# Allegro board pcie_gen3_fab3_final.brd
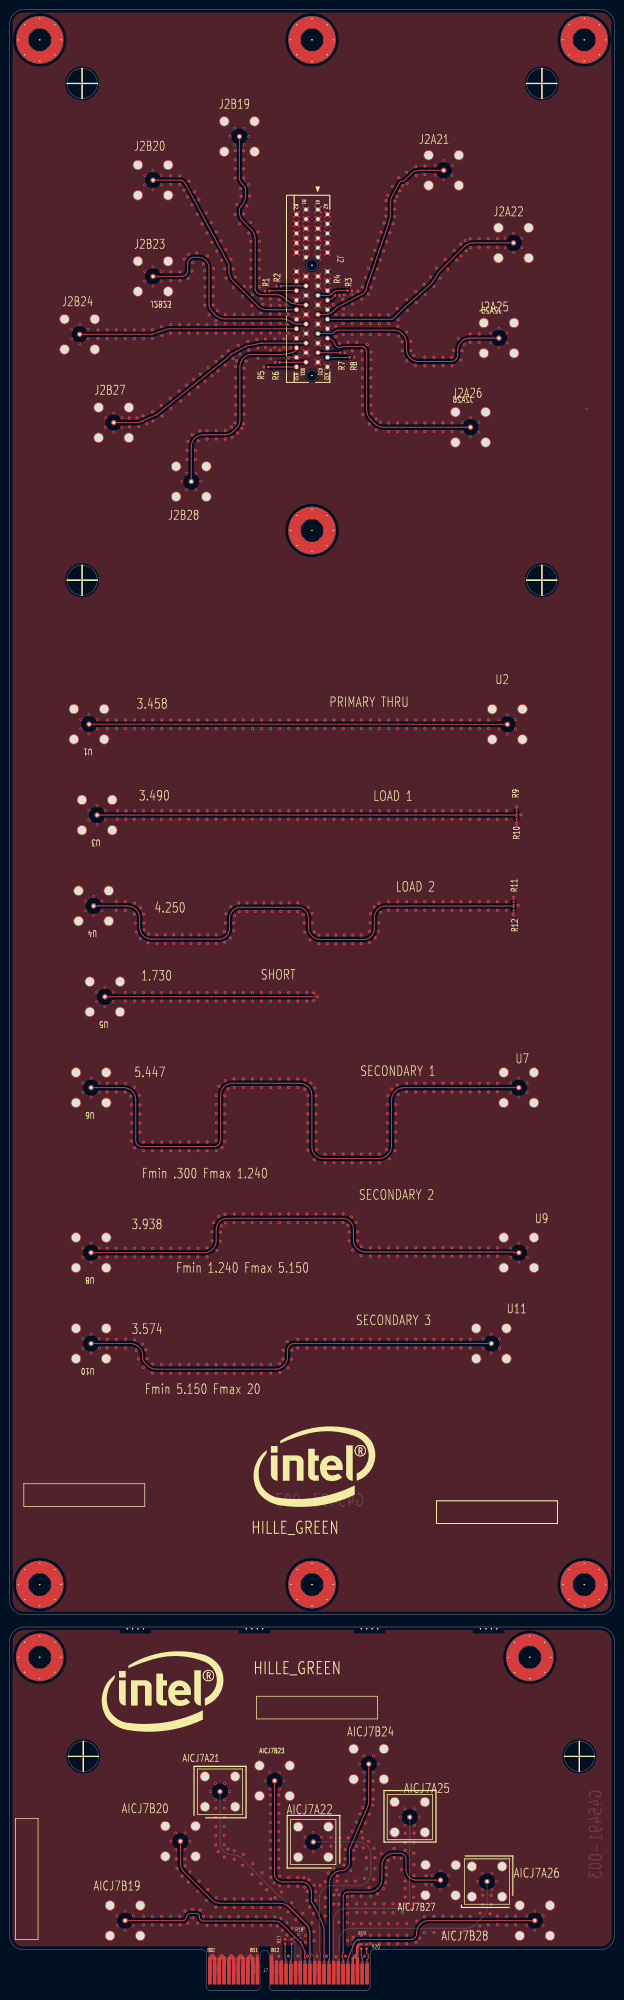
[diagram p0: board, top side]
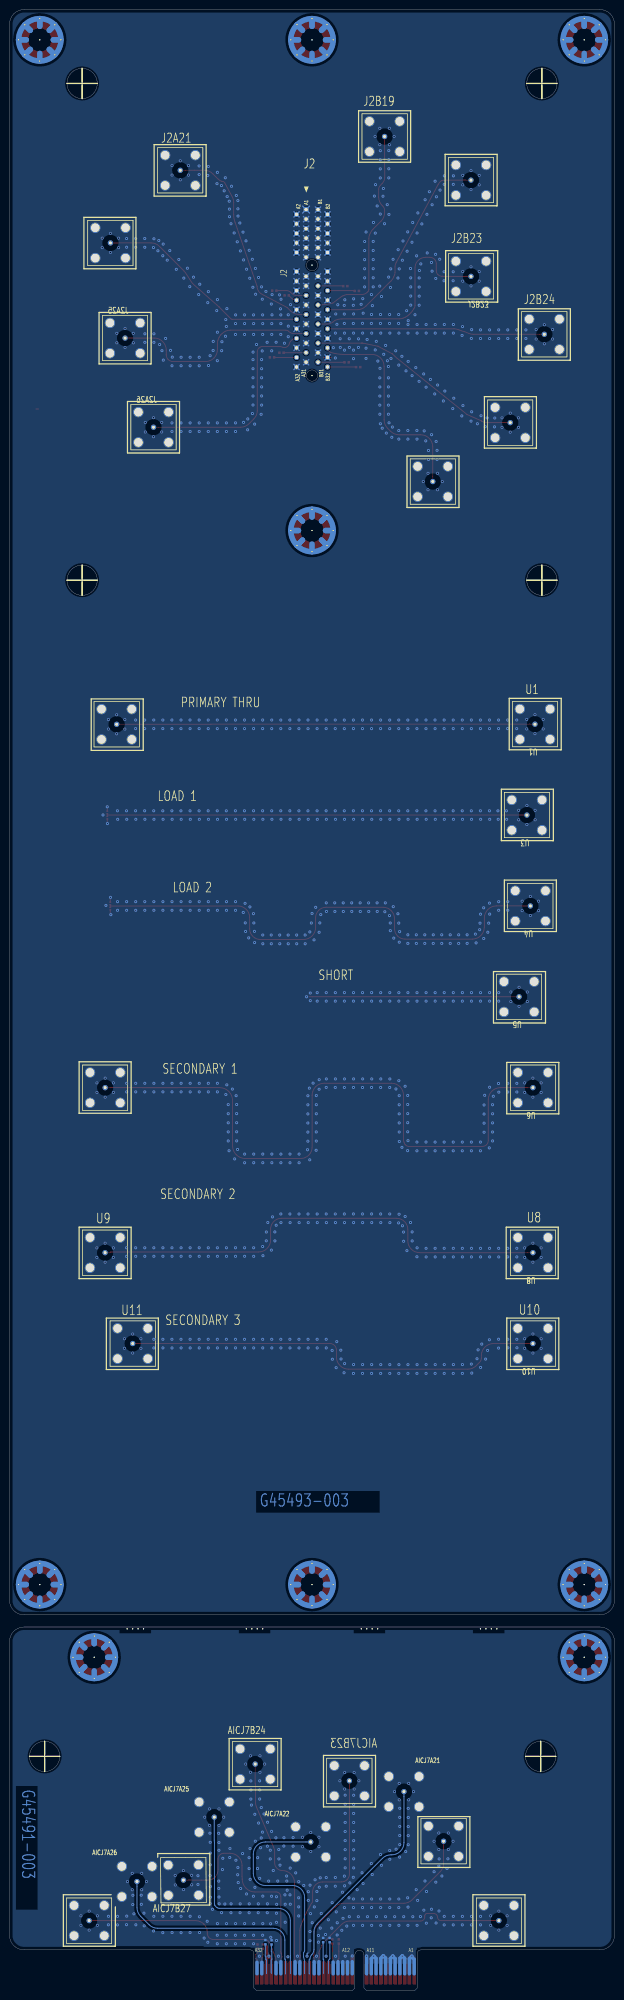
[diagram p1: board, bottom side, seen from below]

Outline 127 x 415.29 mm; copper layers: TOP, LAYER2, LAYER3, BOTTOM. Coordinates in mm from the lower left corner of the outline.
Outline path: 0,412.24 0,81.79 arc(0.89,79.63) 3.05,78.74 123.95,78.74 arc(126.11,79.63) 127,81.79 127,412.24 arc(126.11,414.4) 123.95,415.29 3.05,415.29 arc(0.89,414.4) 0,412.24 ; 0,73.15 0,11.56 arc(0.89,9.4) 3.05,8.51 40.64,8.51 arc(41.17,8.29) 41.4,7.75 41.4,0.51 41.91,0 52.09,0 52.59,0.51 52.59,7.45 arc(52.87,8.13) 53.55,8.41 arc(54.22,8.13) 54.5,7.45 54.5,0.51 55.01,0 75.19,0 75.7,0.51 75.7,7.75 arc(75.92,8.29) 76.46,8.51 123.95,8.51 arc(126.11,9.4) 127,11.56 127,73.15 arc(126.11,75.31) 123.95,76.2 3.05,76.2 arc(0.89,75.31) 0,73.15

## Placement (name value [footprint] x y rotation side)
AICJ7A21  -  [ROSEBERG_2X2_1_R_TH_V]  44.19 41.69 270 top
AICJ7A22  -  [ROSEBERG_2X2_1_R_TH_V]  63.77 31.13 0 top
AICJ7A25  -  [ROSEBERG_2X2_1_R_TH_V]  84.02 36.34 270 top
AICJ7A26  -  [ROSEBERG_2X2_1_R_TH_V]  100.24 22.84 90 top
AICJ7B19  -  [ROSEBERG_2X2_1_R_TH_V]  24.27 14.65 0 bottom
AICJ7B20  -  [ROSEBERG_2X2_1_R_TH_V]  35.88 31.28 270 bottom
AICJ7B23  -  [ROSEBERG_2X2_1_R_TH_V]  55.65 43.95 270 bottom
AICJ7B24  -  [ROSEBERG_2X2_1_R_TH_V]  75.43 47.46 270 bottom
AICJ7B27  -  [ROSEBERG_2X2_1_R_TH_V]  90.49 23.13 179.6 bottom
AICJ7B28  -  [ROSEBERG_2X2_1_R_TH_V]  110.28 14.65 180 bottom
J2  -  [CONN64_TEST]  64.74 373.35 0 top
J2A21  -  [ROSEBERG_2X2_1_R_TH_V]  91.16 381.58 180 bottom
J2A22  -  [ROSEBERG_2X2_1_R_TH_V]  105.82 366.37 180 bottom
J2A25  -  [ROSEBERG_2X2_1_R_TH_V]  102.75 346.42 180 bottom
J2A26  -  [ROSEBERG_2X2_1_R_TH_V]  96.78 327.72 180 bottom
J2B19  -  [ROSEBERG_2X2_1_R_TH_V]  48.26 388.67 270 bottom
J2B20  -  [ROSEBERG_2X2_1_R_TH_V]  30.12 379.53 0 bottom
J2B23  -  [ROSEBERG_2X2_1_R_TH_V]  30.13 359.35 0 bottom
J2B24  -  [ROSEBERG_2X2_1_R_TH_V]  14.72 347.21 0 bottom
J2B27  -  [ROSEBERG_2X2_1_R_TH_V]  21.89 328.69 0 bottom
J2B28  -  [ROSEBERG_2X2_1_R_TH_V]  38.15 316.34 90 bottom
J7  -  [3GIO_X4_GF]  42.05 3.49 0 top
MH1  -  [MTG_SPOKE_N156]  6.35 408.94 0 top
MH2  -  [MTG_SPOKE_N156]  63.5 408.94 0 top
MH3  -  [MTG_SPOKE_N156]  120.65 408.94 0 top
MH4  -  [MTG_SPOKE_N156]  63.5 306.07 0 top
MH5  -  [MTG_SPOKE_N156]  6.35 85.09 0 top
MH6  -  [MTG_SPOKE_N156]  63.5 85.09 0 top
MH7  -  [MTG_SPOKE_N156]  120.65 85.09 0 top
MH8  -  [MTG_SPOKE_N156]  6.35 69.85 0 top
MH9  -  [MTG_SPOKE_N156]  109.22 69.85 0 top
NOREF  -  []  662.31 185.42 0 top
NOREF#2  -  []  105.98 77.47 0 top
NOREF#3  -  []  381.13 58.7 0 top
NOREF#4  -  []  25.07 -11.85 0 top
NOREF#5  -  []  75.74 0.53 0 top
NOREF#6  -  []  410.64 75.67 0 top
NOREF#7  -  []  429.69 75.67 0 top
NOREF#8  -  []  2.93 106.51 0 top
NOREF#9  -  []  25.13 -55.18 0 top
NOREF#10  -  [unnamed#2]  111.76 295.66 0 top
NOREF#11  -  []  378.99 398.49 0 top
NOREF#12  -  []  51.44 79.06 0 top
NOREF#13  -  []  650.88 198.37 0 top
NOREF#14  -  []  382.7 28.68 0 top
NOREF#15  -  []  -110.54 70.33 0 top
NOREF#16  -  [unnamed#2]  111.76 399.8 0 top
NOREF#17  -  []  670.56 186.06 0 top
NOREF#18  -  []  378.78 398.25 0 top
NOREF#19  -  []  651.76 189.31 0 top
NOREF#20  -  []  -279.16 357.38 270 top
NOREF#21  -  []  1.32 35.89 0 top
NOREF#22  -  []  419.28 -16.92 0 top
NOREF#23  -  []  40.46 0.93 0 top
NOREF#24  -  []  102.23 80.26 0 top
NOREF#25  -  []  41.22 7.97 0 top
NOREF#26  -  []  403.89 -29.7 0 top
NOREF#27  -  []  -64.46 384.41 0 top
NOREF#28  -  []  0 11.98 0 top
NOREF#29  -  []  52.64 0.93 0 top
NOREF#30  -  [unnamed#2]  15.24 399.8 0 top
NOREF#31  -  []  127 11.98 0 top
NOREF#32  -  []  89.61 97.89 0 top
NOREF#33  -  []  -258.65 -67.84 0 top
NOREF#34  -  []  650.88 198.37 0 top
NOREF#35  -  []  127 407.67 0 top
NOREF#36  -  []  -0.05 415.29 0 top
NOREF#37  -  []  32.13 62.61 0 top
NOREF#38  -  []  377.83 -5.88 0 top
NOREF#39  -  []  430.47 -16.92 0 top
NOREF#40  -  []  153.03 402.36 90 top
NOREF#41  -  []  26.42 79.06 0 top
NOREF#42  -  [unnamed#2]  15.24 295.66 0 top
NOREF#43  -  []  845.26 89.87 0 top
NOREF#44  -  []  52.6 7.54 0 top
NOREF#45  -  []  -50.39 413.32 7 top
NOREF#46  -  []  2.31 76.2 0 top
NOREF#47  -  []  41.1 4.29 0 top
NOREF#48  -  []  53.52 0.64 0 top
NOREF#49  -  []  -39.83 11.39 0 top
NOREF#50  -  []  -255.09 -81.65 0 top
NOREF#51  -  [unnamed#2]  15.49 49.07 0 top
NOREF#52  -  []  74.24 -0.37 0 top
NOREF#53  -  []  100.58 79.06 0 top
NOREF#54  -  []  25.13 11.39 0 top
NOREF#55  -  []  419.92 -13.56 0 top
NOREF#56  -  []  64.01 109.75 0 top
NOREF#57  -  []  75.56 79.06 0 top
NOREF#58  -  []  380.88 -8.92 0 top
NOREF#59  -  []  272.21 43.92 0 top
NOREF#60  -  []  432.34 -17.22 0 top
NOREF#61  -  []  41.45 0.93 0 top
NOREF#62  -  []  126.38 414.08 0 top
NOREF#63  -  []  -111.23 120.93 0 top
NOREF#64  -  []  453.07 -17.43 0 top
NOREF#65  -  []  2.06 8.51 0 top
NOREF#66  -  []  431.43 -9.98 0 top
NOREF#67  -  []  504.83 -5.88 0 top
NOREF#68  -  [unnamed#2]  119.63 49.07 0 top
NOREF#69  -  []  329.43 547.83 0 top
NOREF#70  -  []  453.55 -17.32 0 top
NOREF#71  -  []  154.42 414.43 0 top
NOREF#72  -  []  405.42 469.29 277 top
NOREF#73  -  []  339 -6.46 0 top
NOREF#74  -  []  403.95 -73.03 0 top
NOREF#75  -  []  403.95 -6.46 0 top
NOREF#76  -  [unnamed#3]  100.58 77.47 0 bottom
NOREF#77  -  [unnamed#3]  26.42 77.47 0 bottom
NOREF#78  -  [unnamed#3]  75.56 77.47 0 bottom
NOREF#79  -  [unnamed#3]  51.44 77.47 0 bottom
R1  42.2  [SMR0402A]  53.65 356.29 90 top
R2  42.2  [SMR0402A]  56.06 357.31 90 top
R3  42.2  [SMR0402A]  70.97 356.35 90 top
R4  42.2  [SMR0402A]  68.37 355.36 90 top
R5  42.2  [SMR0402A]  53.37 340.33 90 top
R6  42.2  [SMR0402A]  55.78 341.33 90 top
R7  42.2  [SMR0402A]  69.46 343.35 90 top
R8  42.2  [SMR0402A]  71.46 342.37 90 top
R9  85  [SMR0201NC]  106.47 246.7 180 top
R10  85  [SMR0201NC]  106.47 246.14 0 top
R11  85  [SMR0201NC]  105.85 227.62 180 top
R12  85  [SMR0201NC]  105.85 227.06 0 top
R17  42.2  [SMR0402A]  57.87 10.71 0 top
R18  42.2  [SMR0402A]  59.22 10.71 0 top
R19  42.2  [SMR0402A]  73.83 9.64 0 top
R20  42.2  [SMR0402A]  74.95 9.64 0 top
R25  42.2  [SMR0402A]  59.8 10.12 0 bottom
R26  42.2  [SMR0402A]  61.16 10.12 0 bottom
R27  42.2  [SMR0402A]  71.99 9.63 0 bottom
R28  42.2  [SMR0402A]  73.29 9.68 0 bottom
U1  -  [ROSEBERG_2X2_1_R_TH_V]  16.69 265.47 0 bottom
U2  -  [ROSEBERG_2X2_1_R_TH_V]  104.51 265.44 180 bottom
U3  -  [ROSEBERG_2X2_1_R_TH_V]  18.39 246.42 0 bottom
U4  -  [ROSEBERG_2X2_1_R_TH_V]  17.66 227.37 0 bottom
U5  -  [ROSEBERG_2X2_1_R_TH_V]  20.03 208.32 0 bottom
U6  -  [ROSEBERG_2X2_1_R_TH_V]  17.12 189.27 0 bottom
U7  -  [ROSEBERG_2X2_1_R_TH_V]  106.92 189.27 180 bottom
U8  -  [ROSEBERG_2X2_1_R_TH_V]  17.12 154.67 0 bottom
U9  -  [ROSEBERG_2X2_1_R_TH_V]  106.94 154.67 180 bottom
U10  -  [ROSEBERG_2X2_1_R_TH_V]  17.12 135.62 0 bottom
U11  -  [ROSEBERG_2X2_1_R_TH_V]  101.15 135.62 180 bottom

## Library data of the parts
AICJ7A21 AICJ7B19 AICJ7B20 AICJ7B23 AICJ7B24 AICJ7B27 AICJ7B28 J2A21 J2A22 J2A25 J2A26 U1-U11 = CONN_SMA_LOCAL: part number: CONN_SMA_LOCAL_THLF-EMPTY,700000-903
AICJ7A22 AICJ7A25 AICJ7A26 J2B19 J2B20 J2B23 J2B24 J2B27 J2B28 = CONN_SMA_LOCAL: part number: CONN_SMA_LOCAL_THLF-CONN,700000-903
J2 = CONN64_TEST: part number: CONN64_TEST_THLF-CONN,A96883-002,CONN64_TEST
J7 = CONN64_TEST: part number: CONN64_TEST_NO_BOM-FINGERS,NO_BOM,CONN64_TEST
MH1-MH9 = MTG_SPOKE_N156: alternate symbols: (MTG_SPOKE_N156A,MTG_SPOKE_N156B); part number: MTG_SPOKE_N156_TH-EMPTY,N_A
R1-R8 R17-R20 R25-R28 = RES: alternate symbols: (SMR0402A); part number: RES_0402LF-42.2,1%,1/16W,CHIP,A47430-014; tolerance: 1%
R9-R12 = RES0201: part number: RES0201_DFMNC-85,1%,1/20W,CHIP,C48657-108; tolerance: 1%

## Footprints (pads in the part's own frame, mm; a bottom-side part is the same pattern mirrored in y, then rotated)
3GIO_X4_GF
  rect 0.711x4.288 smd: A1(0,0) A2(1,0) A3(2,0) A4(3,0) A5(4,0) A6(5,0) A7(6,0) A8(7,0) A9(8,0) A10(9,0) A11(10,0) A12(13,0) A13(14,0) A14(15,0) A15(16,0) A16(17,0) A17(18,0) A18(19,0) A19(20,0) A20(21,0) A21(22,0) A22(23,0) A23(24,0) A24(25,0) A25(26,0) A26(27,0) A27(28,0) A28(29,0) A29(30,0) A30(31,0) A31(32,0) A32(33,0) B1(0,0) B2(1,0) B3(2,0) B4(3,0) B5(4,0) B6(5,0) B7(6,0) B8(7,0) B9(8,0) B10(9,0) B11(10,0) B12(13,0) B13(14,0) B14(15,0) B15(16,0) B16(17,0) B17(18,0) B18(19,0) B19(20,0) B20(21,0) B21(22,0) B22(23,0) B23(24,0) B24(25,0) B25(26,0) B26(27,0) B27(28,0) B28(29,0) B29(30,0) B30(31,0) B31(32,0) B32(33,0)
CONN64_TEST
  round 0.254 hole 2.362 unplated: (-1.25,-11.65) (-1.25,-34.8)
  rect 1.092x1.092 hole 0.711: A1(0,0)
  round 1.092 hole 0.711: A2(2,-1) A3(0,-2) A4(2,-3) A5(0,-4) A6(2,-5) A7(0,-6) A8(2,-7) A9(0,-8) A10(2,-9) A11(0,-10) A12(2,-13) A13(0,-14) A14(2,-15) A15(0,-16) A16(2,-17) A17(0,-18) A18(2,-19) A19(0,-20) A20(2,-21) A21(0,-22) A22(2,-23) A23(0,-24) A24(2,-25) A25(0,-26) A26(2,-27) A27(0,-28) A28(2,-29) A29(0,-30) A30(2,-31) A31(0,-32) A32(2,-33) B1(-2.5,0) B2(-4.5,-1) B3(-2.5,-2) B4(-4.5,-3) B5(-2.5,-4) B6(-4.5,-5) B7(-2.5,-6) B8(-4.5,-7) B9(-2.5,-8) B10(-4.5,-9) B11(-2.5,-10) B12(-4.5,-13) B13(-2.5,-14) B14(-4.5,-15) B15(-2.5,-16) B16(-4.5,-17) B17(-2.5,-18) B18(-4.5,-19) B19(-2.5,-20) B20(-4.5,-21) B21(-2.5,-22) B22(-4.5,-23) B23(-2.5,-24) B24(-4.5,-25) B25(-2.5,-26) B26(-4.5,-27) B27(-2.5,-28) B28(-4.5,-29) B29(-2.5,-30) B30(-4.5,-31) B31(-2.5,-32) B32(-4.5,-33)
MTG_SPOKE_N156
  round 0.254 hole 3.962 unplated: (0,0)
  round 0.635 hole 0.254: 1(0,4.445) 2(3.15,3.15) 3(4.445,0) 4(3.15,-3.15) 5(0,-4.445) 6(-3.15,-3.15) 7(-4.445,0) 8(-3.15,3.15)
ROSEBERG_2X2_1_R_TH_V
  round 1.118 hole 0.61: 1(0,0)
  round 2.159 hole 1.778: MH1(3.175,3.175) MH2(3.175,-3.175) MH3(-3.175,-3.175) MH4(-3.175,3.175)
SMR0201NC
  rect 0.381x0.305 smd: 1(0,0) 2(0,-0.533)
SMR0402A
  rect 0.508x0.508 smd: 1(0,0) 2(0,-0.889)
unnamed#2
  round 0.254 hole 6.35 unplated: (0,0)
unnamed#3
  round 0.254 hole 0.635 unplated: (-1.714,1.651) (-0.572,1.651) (0.572,1.651) (1.714,1.651)

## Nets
GND_BASELINE: AICJ7A21.MH1 AICJ7A21.MH2 AICJ7A21.MH3 AICJ7A21.MH4 AICJ7A22.MH1 AICJ7A22.MH2 AICJ7A22.MH3 AICJ7A22.MH4 AICJ7A25.MH1 AICJ7A25.MH2 AICJ7A25.MH3 AICJ7A25.MH4 AICJ7A26.MH1 AICJ7A26.MH2 AICJ7A26.MH3 AICJ7A26.MH4 AICJ7B19.MH1 AICJ7B19.MH2 AICJ7B19.MH3 AICJ7B19.MH4 AICJ7B20.MH1 AICJ7B20.MH2 AICJ7B20.MH3 AICJ7B20.MH4 AICJ7B23.MH1 AICJ7B23.MH2 AICJ7B23.MH3 AICJ7B23.MH4 AICJ7B24.MH1 AICJ7B24.MH2 AICJ7B24.MH3 AICJ7B24.MH4 AICJ7B27.MH1 AICJ7B27.MH2 AICJ7B27.MH3 AICJ7B27.MH4 AICJ7B28.MH1 AICJ7B28.MH2 AICJ7B28.MH3 AICJ7B28.MH4 J2.A1(GND45) J2.A2(GND44) J2.A3(GND43) J2.A4(GND42) J2.A5(GND41) J2.A6(GND40) J2.A7(GND39) J2.A8(GND38) J2.A9(GND37) J2.A10(GND36) J2.A11(GND35) J2.A12(GND34) J2.A13(GND33) J2.A14(GND32) J2.A15(GND31) J2.A16(GND30) J2.A19(GND29) J2.A20(GND28) J2.A23(GND27) J2.A24(GND26) J2.A27(GND25) J2.A28(GND24) J2.A31(GND23) J2.A32(GND22) J2.B1(GND0) J2.B2(GND1) J2.B3(GND2) J2.B4(GND3) J2.B5(GND4) J2.B6(GND5) J2.B7(GND6) J2.B8(GND7) J2.B9(GND8) J2.B10(GND9) J2.B11(GND10) J2.B12(GND11) J2.B13(GND12) J2.B14(GND13) J2.B17(GND14) J2.B18(GND15) J2.B21(GND16) J2.B22(GND17) J2.B25(GND18) J2.B26(GND19) J2.B29(GND20) J2.B30(GND21) J2A21.MH1 J2A21.MH2 J2A21.MH3 J2A21.MH4 J2A22.MH1 J2A22.MH2 J2A22.MH3 J2A22.MH4 J2A25.MH1 J2A25.MH2 J2A25.MH3 J2A25.MH4 J2A26.MH1 J2A26.MH2 J2A26.MH3 J2A26.MH4 J2B19.MH1 J2B19.MH2 J2B19.MH3 J2B19.MH4 J2B20.MH1 J2B20.MH2 J2B20.MH3 J2B20.MH4 J2B23.MH1 J2B23.MH2 J2B23.MH3 J2B23.MH4 J2B24.MH1 J2B24.MH2 J2B24.MH3 J2B24.MH4 J2B27.MH1 J2B27.MH2 J2B27.MH3 J2B27.MH4 J2B28.MH1 J2B28.MH2 J2B28.MH3 J2B28.MH4 J7.A1(GND45) J7.A2(GND44) J7.A3(GND43) J7.A4(GND42) J7.A5(GND41) J7.A6(GND40) J7.A7(GND39) J7.A8(GND38) J7.A9(GND37) J7.A10(GND36) J7.A11(GND35) J7.A12(GND34) J7.A13(GND33) J7.A14(GND32) J7.A15(GND31) J7.A16(GND30) J7.A19(GND29) J7.A20(GND28) J7.A23(GND27) J7.A24(GND26) J7.A27(GND25) J7.A28(GND24) J7.A31(GND23) J7.A32(GND22) J7.B1(GND0) J7.B2(GND1) J7.B3(GND2) J7.B4(GND3) J7.B5(GND4) J7.B6(GND5) J7.B7(GND6) J7.B8(GND7) J7.B9(GND8) J7.B10(GND9) J7.B11(GND10) J7.B12(GND11) J7.B13(GND12) J7.B14(GND13) J7.B17(GND14) J7.B18(GND15) J7.B21(GND16) J7.B22(GND17) J7.B25(GND18) J7.B26(GND19) J7.B29(GND20) J7.B30(GND21) MH1.1(P1) MH1.2(P2) MH1.3(P3) MH1.4(P4) MH1.5(P5) MH1.6(P6) MH1.7(P7) MH1.8(P8) MH2.1(P1) MH2.2(P2) MH2.3(P3) MH2.4(P4) MH2.5(P5) MH2.6(P6) MH2.7(P7) MH2.8(P8) MH3.1(P1) MH3.2(P2) MH3.3(P3) MH3.4(P4) MH3.5(P5) MH3.6(P6) MH3.7(P7) MH3.8(P8) MH4.1(P1) MH4.2(P2) MH4.3(P3) MH4.4(P4) MH4.5(P5) MH4.6(P6) MH4.7(P7) MH4.8(P8) MH5.1(P1) MH5.2(P2) MH5.3(P3) MH5.4(P4) MH5.5(P5) MH5.6(P6) MH5.7(P7) MH5.8(P8) MH6.1(P1) MH6.2(P2) MH6.3(P3) MH6.4(P4) MH6.5(P5) MH6.6(P6) MH6.7(P7) MH6.8(P8) MH7.1(P1) MH7.2(P2) MH7.3(P3) MH7.4(P4) MH7.5(P5) MH7.6(P6) MH7.7(P7) MH7.8(P8) MH8.1(P1) MH8.2(P2) MH8.3(P3) MH8.4(P4) MH8.5(P5) MH8.6(P6) MH8.7(P7) MH8.8(P8) MH9.1(P1) MH9.2(P2) MH9.3(P3) MH9.4(P4) MH9.5(P5) MH9.6(P6) MH9.7(P7) MH9.8(P8) R1.1(A) R2.1(A) R3.2(B) R4.2(B) R5.1(A) R6.1(A) R7.2(B) R8.2(B) R9.2(B) R10.2(B) R11.2(B) R12.2(B) R17.1(A) R18.1(A) R19.1(A) R20.1(A) R25.2(B) R26.2(B) R27.2(B) R28.2(B) U1.MH1 U1.MH2 U1.MH3 U1.MH4 U2.MH1 U2.MH2 U2.MH3 U2.MH4 U3.MH1 U3.MH2 U3.MH3 U3.MH4 U4.MH1 U4.MH2 U4.MH3 U4.MH4 U5.MH1 U5.MH2 U5.MH3 U5.MH4 U6.MH1 U6.MH2 U6.MH3 U6.MH4 U7.MH1 U7.MH2 U7.MH3 U7.MH4 U8.MH1 U8.MH2 U8.MH3 U8.MH4 U9.MH1 U9.MH2 U9.MH3 U9.MH4 U10.MH1 U10.MH2 U10.MH3 U10.MH4 U11.MH1 U11.MH2 U11.MH3 U11.MH4
LOAD1: R9.1(A) R10.1(A) U3.1(IO1)
LOAD2: R11.1(A) R12.1(A) U4.1(IO1)
PRIMARY_THRU: U1.1(IO1) U2.1(IO1)
R_T1_CONN: J2.B15(TEST1) R2.2(B)
R_T1_EDGE: J7.B15(TEST1) R17.2(B)
R_T2_CONN: J2.B16(TEST2) R1.2(B)
R_T2_EDGE: J7.B16(TEST2) R18.2(B)
R_T9_CONN: J2.B31(TEST9) R6.2(B)
R_T9_EDGE: J7.B31(TEST9) R19.2(B)
R_T10_CONN: J2.B32(TEST10) R5.2(B)
R_T10_EDGE: J7.B32(TEST10) R20.2(B)
R_T11_CONN: J2.A30(TEST11) R8.1(A)
R_T11_EDGE: J7.A30(TEST11) R28.1(A)
R_T12_CONN: J2.A29(TEST12) R7.1(A)
R_T12_EDGE: J7.A29(TEST12) R27.1(A)
R_T17_EDGE: J7.A18(TEST17) R26.1(A)
R_T18_EDGE: J7.A17(TEST18) R25.1(A)
SECONDARY1: U6.1(IO1) U7.1(IO1)
SECONDARY2: U8.1(IO1) U9.1(IO1)
SECONDARY3: U10.1(IO1) U11.1(IO1)
SHORT: U5.1(IO1)
T3_EDGE: AICJ7B19.1(IO1) J7.B19(TEST3)
T4_EDGE: AICJ7B20.1(IO1) J7.B20(TEST4)
T5_EDGE: AICJ7B23.1(IO1) J7.B23(TEST5)
T6_EDGE: AICJ7B24.1(IO1) J7.B24(TEST6)
T7_EDGE: AICJ7B27.1(IO1) J7.B27(TEST7)
T8_EDGE: AICJ7B28.1(IO1) J7.B28(TEST8)
T13_EDGE: AICJ7A26.1(IO1) J7.A26(TEST13)
T14_EDGE: AICJ7A25.1(IO1) J7.A25(TEST14)
T15_EDGE: AICJ7A22.1(IO1) J7.A22(TEST15)
T16_EDGE: AICJ7A21.1(IO1) J7.A21(TEST16)
TEST3_CONN: J2.B19(TEST3) J2B19.1(IO1)
TEST4_CONN: J2.B20(TEST4) J2B20.1(IO1)
TEST5_CONN: J2.B23(TEST5) J2B23.1(IO1)
TEST6_CONN: J2.B24(TEST6) J2B24.1(IO1)
TEST7_CONN: J2.B27(TEST7) J2B27.1(IO1)
TEST8_CONN: J2.B28(TEST8) J2B28.1(IO1)
TEST13_CONN: J2.A26(TEST13) J2A26.1(IO1)
TEST14_CONN: J2.A25(TEST14) J2A25.1(IO1)
TEST15_CONN: J2.A22(TEST15) J2A22.1(IO1)
TEST16_CONN: J2.A21(TEST16) J2A21.1(IO1)
TEST17_CONN: J2.A18(TEST17) R4.1(A)
TEST18_CONN: J2.A17(TEST18) R3.1(A)

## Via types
v1: diameter 0.635, hole 0.254, TOP to BOTTOM, 1359 vias
v2: diameter 0.61, hole 0.356, TOP to BOTTOM, 186 vias

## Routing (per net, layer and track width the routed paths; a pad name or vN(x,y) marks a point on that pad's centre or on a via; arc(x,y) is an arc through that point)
GND_BASELINE: length 975.4
  TOP w0.184: v1(105.73,225.54) 105.85,225.65 R12.2 ; R11.2 105.85,229.12 v1(105.8,229.16) ; v1(106.45,244.63) 106.47,244.65 R10.2 ; R9.2 106.47,248.14 v1(106.48,248.15)
  TOP w0.254: 64.18,352.79 J2.A19 ; J2.A19 65.31,352.79 ; J2.A19 64.18,353.92 ; J2.A19 65.31,353.92 ; 61.68,363.92 J2.B11 ; J2.B11 62.81,363.92 ; J2.B11 61.68,362.79 ; 66.18,340.92 J2.A32 ; J2.A32 67.31,340.92 ; J2.A32 66.18,339.79 ; J2.A32 67.31,339.79 ; 61.68,368.79 J2.B5 ; J2.B5 62.81,368.79 ; J2.B5 62.81,369.92 ; J2.B5 61.68,369.92 ; 60.81,354.92 J2.B18 59.68,354.92 ; J2.A27 65.31,345.92 ; J2.A27 65.31,344.79 ; J2.A27 64.18,345.92 ; J2.A27 64.18,344.79 ; J2.A13 65.31,358.79 ; J2.A13 64.18,359.92 ; J2.A13 65.31,359.92 ; J2.A13 64.18,358.79 ; J2.A7 65.31,367.92 ; J2.A7 65.31,366.79 ; J2.A7 64.18,366.79 ; J2.A7 64.18,367.92 ; 64.18,349.92 J2.A23 ; J2.A23 65.31,349.92 ; J2.A23 65.31,348.79 ; J2.A23 64.18,348.79 ; 66.18,363.79 J2.A10 ; J2.A10 66.18,364.92 ; J2.A10 67.31,363.79 ; J2.A10 67.31,364.92 ; J2.A4 67.31,369.79 ; J2.A4 66.18,369.79 ; J2.A4 66.18,370.92 ; J2.A4 67.31,370.92 ; 59.68,350.92 J2.B22 60.81,350.92 ; J2.A1 65.47,372.63 ; J2.A1 65.47,374.08 ; J2.A1 64.02,372.63 ; J2.A1 64.02,374.08 ; J2.A8 67.31,366.92 ; J2.A8 66.18,365.79 ; J2.A8 66.18,366.92 ; J2.A8 67.31,365.79 ; 59.68,366.92 J2.B8 ; J2.B8 60.81,366.92 ; J2.B8 59.68,365.79 ; J2.B8 60.81,365.79 ; J2.B9 62.81,364.79 ; J2.B9 61.68,365.92 ; J2.B9 62.81,365.92 ; J2.B9 61.68,364.79 ; 67.31,352.92 J2.A20 66.18,352.92 ; 61.68,371.92 J2.B3 ; J2.B3 62.81,371.92 ; J2.B3 62.81,370.79 ; J2.B3 61.68,370.79 ; 66.18,367.79 J2.A6 ; J2.A6 67.31,368.92 ; J2.A6 67.31,367.79 ; J2.A6 66.18,368.92 ; 61.68,355.92 J2.B17 ; J2.B17 62.81,354.79 ; J2.B17 62.81,355.92 ; J2.B17 61.68,354.79 ; 64.18,369.92 J2.A5 ; J2.A5 64.18,368.79 ; J2.A5 65.31,369.92 ; J2.A5 65.31,368.79 ; J2.A15 65.31,357.92 ; J2.A15 64.18,357.92 ; J2.A15 65.31,356.79 ; J2.A15 64.18,356.79 ; 59.68,367.79 J2.B6 ; J2.B6 60.81,368.92 ; J2.B6 60.81,367.79 ; J2.B6 59.68,368.92 ; J2.A31 65.31,340.79 ; J2.A31 65.31,341.92 ; J2.A31 64.18,340.79 ; J2.A31 64.18,341.92 ; 59.68,360.92 J2.B12 ; J2.B12 60.81,360.92 ; J2.B12 59.68,359.79 ; J2.B12 60.81,359.79 ; 61.68,359.92 J2.B13 ; J2.B13 62.81,359.92 ; J2.B13 62.81,358.79 ; J2.B13 61.68,358.79 ; 59.68,370.92 J2.B4 ; J2.B4 59.68,369.79 ; J2.B4 60.81,370.92 ; J2.B4 60.81,369.79 ; J2.B2 60.81,372.92 ; J2.B2 60.81,371.79 ; J2.B2 59.68,372.92 ; J2.B2 59.68,371.79 ; 61.01,342.35 J2.B30 59.48,342.35 ; 61.68,367.92 J2.B7 ; J2.B7 62.81,367.92 ; J2.B7 62.81,366.79 ; J2.B7 61.68,366.79 ; J2.B1 62.81,372.79 ; J2.B1 62.81,373.92 ; J2.B1 61.68,372.79 ; J2.B1 61.68,373.92 ; 66.18,356.92 J2.A16 67.31,356.92 ; 66.18,357.79 J2.A14 ; J2.A14 66.18,358.92 ; J2.A14 67.31,358.92 ; J2.A14 67.31,357.79 ; J2.B25 62.81,347.92 ; J2.B25 61.68,346.79 ; J2.B25 61.68,347.92 ; J2.B25 62.81,346.79 ; J2.B10 60.81,363.79 ; J2.B10 59.68,364.92 ; J2.B10 60.81,364.92 ; J2.B10 59.68,363.79 ; J2.A11 65.31,362.79 ; J2.A11 65.31,363.92 ; J2.A11 64.18,363.92 ; J2.A2 67.31,371.79 ; J2.A2 66.18,371.79 ; J2.A2 67.31,372.92 ; J2.A2 66.18,372.92 ; 61.68,351.92 J2.B21 ; J2.B21 61.68,350.79 ; J2.B21 62.81,351.92 ; J2.B21 62.81,350.79 ; 59.68,346.92 J2.B26 60.81,346.92 ; 64.18,371.92 J2.A3 ; J2.A3 64.18,370.79 ; J2.A3 65.31,370.79 ; J2.A3 65.31,371.92 ; 66.18,359.79 J2.A12 ; J2.A12 67.31,359.79 ; J2.A12 67.31,360.92 ; J2.A12 66.18,360.92 ; 67.31,344.92 J2.A28 66.18,344.92 ; J2.A9 65.31,364.79 ; J2.A9 64.18,365.92 ; J2.A9 65.31,365.92 ; J2.A9 64.18,364.79 ; 61.68,343.92 J2.B29 ; J2.B29 62.81,342.79 ; J2.B29 61.68,342.79 ; J2.B29 62.81,343.92 ; 66.18,348.92 J2.A24 67.31,348.92 ; 59.68,358.92 J2.B14 60.81,358.92
  TOP w0.508: v1(55.04,7.22) 55.05,7.22 ; 73.24,9.59 73.24,9.43 73.04,9.23 73.04,9.14 73,9.1 72.99,8.06 72.74,7.19 v1(72.55,7.19) 72.05,6.69 J7.B29
  TOP w0.711: J7.A7 48.05,6.7 v1(48.54,7.19) 49.05,6.68 J7.A8 ; J7.A11 v1(52.05,7.19) ; J7.A4 45.05,6.74 44.63,7.16 ; 55.05,7.22 J7.A12 ; J7.B18 61.05,5.91 ; J7.A10 51.05,6.69 v1(50.55,7.19) 50.05,6.69 J7.A9 ; 44.63,7.16 44.05,6.58 J7.A3 ; 44.63,7.16 v1(44.55,7.19) ; 46.57,7.1 47.05,6.62 J7.A6 ; 46.57,7.1 46.05,6.58 J7.A5 ; 46.57,7.1 v1(46.56,7.19) ; 42.6,7.21 v1(42.53,7.19) ; 42.6,7.21 43.05,6.76 J7.A2 ; 42.6,7.21 42.05,6.66 J7.A1 ; J7.A13 56.05,5.91 ; J7.B21 64.05,5.91 ; J7.A14 57.05,5.91 ; J7.B30 73.05,6.69 v1(72.55,7.19) ; J7.B17 60.05,5.91 ; J7.B25 68.05,5.91 ; J7.B26 69.05,5.91 ; J7.B22 65.05,5.91
  LAYER2 w0.254: 123.4,406.19 MH3.4 ; MH3.4 124.2,405.39 ; MH3.4 123.4,405.39 ; MH3.4 124.2,406.19 ; MH1.7 2.3,408.54 ; MH1.7 2.3,409.34 ; MH1.7 1.51,409.34 ; MH1.7 1.51,408.54 ; 123.4,412.49 MH3.2 ; MH3.2 124.2,411.69 ; MH3.2 123.4,411.69 ; MH3.2 124.2,412.49 ; J2.B25 62.81,347.92 ; J2.B25 62.81,346.79 ; J2.B25 61.68,346.79 ; J2.B25 61.68,347.92 ; 120.25,412.99 MH3.1 ; MH3.1 120.25,413.78 ; MH3.1 121.05,412.99 ; MH3.1 121.05,413.78 ; 59.68,358.92 J2.B14 ; J2.B14 60.81,357.79 ; J2.B14 60.81,358.92 ; J2.B14 59.68,357.79 ; 59.68,367.79 J2.B6 ; J2.B6 60.81,367.79 ; J2.B6 59.68,368.92 ; J2.B6 60.81,368.92 ; J2.A9 65.31,365.92 ; J2.A9 65.31,364.79 ; J2.A9 64.18,365.92 ; J2.A9 64.18,364.79 ; MH5.3 11.19,85.49 ; MH5.3 11.19,84.69 ; MH5.3 10.4,85.49 ; MH5.3 10.4,84.69 ; 66.18,355.79 J2.A16 ; J2.A16 66.18,356.92 ; J2.A16 67.31,356.92 ; J2.A16 67.31,355.79 ; 120.65,404.5 121.05,404.1 ; 120.65,404.5 120.25,404.1 ; 120.65,404.5 120.25,404.89 ; 120.65,404.5 121.05,404.89 ; 5.95,413.78 MH1.1 ; MH1.1 6.75,413.78 ; MH1.1 6.75,412.99 ; MH1.1 5.95,412.99 ; 2.8,82.34 MH5.6 ; MH5.6 3.6,81.54 ; MH5.6 2.8,81.54 ; MH5.6 3.6,82.34 ; 59.68,363.79 J2.B10 ; J2.B10 59.68,364.92 ; J2.B10 60.81,363.79 ; J2.B10 60.81,364.92 ; 63.1,413.78 MH2.1 ; MH2.1 63.1,412.99 ; MH2.1 63.9,413.78 ; MH2.1 63.9,412.99 ; 67.55,408.54 MH2.3 ; MH2.3 67.55,409.34 ; MH2.3 68.34,409.34 ; MH2.3 68.34,408.54 ; MH7.2 124.2,87.84 ; MH7.2 124.2,88.64 ; MH7.2 123.4,87.84 ; MH7.2 123.4,88.64 ; MH1.4 9.9,406.19 ; MH1.4 9.9,405.39 ; MH1.4 9.1,406.19 ; MH1.4 9.1,405.39 ; MH7.5 121.05,80.25 ; MH7.5 121.05,81.04 ; MH7.5 120.25,81.04 ; MH7.5 120.25,80.25 ; 64.18,367.92 J2.A7 ; J2.A7 65.31,366.79 ; J2.A7 65.31,367.92 ; J2.A7 64.18,366.79 ; MH7.6 117.9,81.54 ; MH7.6 117.9,82.34 ; MH7.6 117.1,81.54 ; MH7.6 117.1,82.34 ; J2.A28 67.31,343.79 ; J2.A28 67.31,344.92 ; J2.A28 66.18,344.92 ; J2.A28 66.18,343.79 ; 117.1,412.49 MH3.8 ; MH3.8 117.9,411.69 ; MH3.8 117.1,411.69 ; MH3.8 117.9,412.49 ; 58.66,85.49 MH6.7 ; MH6.7 58.66,84.69 ; MH6.7 59.45,85.49 ; MH6.7 59.45,84.69 ; 116.2,408.94 116.6,408.54 ; 116.2,408.94 115.81,408.54 ; 116.2,408.94 116.6,409.34 ; 116.2,408.94 115.81,409.34 ; J2.A13 65.31,359.92 ; J2.A13 65.31,358.79 ; J2.A13 64.18,358.79 ; J2.A13 64.18,359.92 ; J2.A19 65.31,352.79 ; J2.A19 64.18,352.79 ; J2.A19 65.31,353.92 ; J2.A19 64.18,353.92 ; 64.18,357.92 J2.A15 ; J2.A15 65.31,357.92 ; J2.A15 65.31,356.79 ; J2.A15 64.18,356.79 ; MH6.5 63.9,80.25 ; MH6.5 63.9,81.04 ; MH6.5 63.1,81.04 ; MH6.5 63.1,80.25 ; MH7.4 124.2,81.54 ; MH7.4 124.2,82.34 ; MH7.4 123.4,82.34 ; MH7.4 123.4,81.54 ; 61.68,363.92 J2.B11 ; J2.B11 61.68,362.79 ; J2.B11 62.81,363.92 ; J2.B2 60.81,371.79 ; J2.B2 60.81,372.92 ; J2.B2 59.68,372.92 ; J2.B2 59.68,371.79 ; 63.1,89.93 MH6.1 ; MH6.1 63.9,89.93 ; MH6.1 63.9,89.14 ; MH6.1 63.1,89.14 ; 115.81,84.69 116.2,85.09 ; 116.2,85.09 116.6,84.69 ; 116.2,85.09 115.81,85.49 ; 116.2,85.09 116.6,85.49 ; 120.25,89.14 MH7.1 ; MH7.1 121.05,89.93 ; MH7.1 120.25,89.93 ; MH7.1 121.05,89.14 ; 64.18,341.92 J2.A31 ; J2.A31 65.31,340.79 ; J2.A31 64.18,340.79 ; J2.A31 65.31,341.92 ; J2.B7 62.81,367.92 ; J2.B7 61.68,367.92 ; J2.B7 61.68,366.79 ; J2.B7 62.81,366.79 ; J2.B12 60.81,359.79 ; J2.B12 60.81,360.92 ; J2.B12 59.68,360.92 ; J2.B12 59.68,359.79 ; 59.68,349.79 J2.B22 ; J2.B22 59.68,350.92 ; J2.B22 60.81,349.79 ; J2.B22 60.81,350.92 ; 66.18,358.92 J2.A14 ; J2.A14 66.18,357.79 ; J2.A14 67.31,358.92 ; J2.A14 67.31,357.79 ; 61.68,370.79 J2.B3 ; J2.B3 61.68,371.92 ; J2.B3 62.81,371.92 ; J2.B3 62.81,370.79 ; MH5.4 9.9,82.34 ; MH5.4 9.1,81.54 ; MH5.4 9.9,81.54 ; MH5.4 9.1,82.34 ; 61.68,342.79 J2.B29 ; J2.B29 62.81,343.92 ; J2.B29 61.68,343.92 ; J2.B29 62.81,342.79 ; J2.B9 62.81,364.79 ; J2.B9 62.81,365.92 ; J2.B9 61.68,365.92 ; J2.B9 61.68,364.79 ; 58.66,409.34 MH2.7 ; MH2.7 59.45,408.54 ; MH2.7 58.66,408.54 ; MH2.7 59.45,409.34 ; 66.25,309.62 MH4.2 ; MH4.2 67.05,308.82 ; MH4.2 67.05,309.62 ; MH4.2 66.25,308.82 ; 64.18,373.92 J2.A1 ; J2.A1 65.31,373.92 ; J2.A1 64.18,372.79 ; J2.A1 65.31,372.79 ; 5.95,89.14 MH5.1 ; MH5.1 6.75,89.93 ; MH5.1 5.95,89.93 ; MH5.1 6.75,89.14 ; 6.35,404.5 6.75,404.1 ; 6.35,404.5 6.75,404.89 ; 6.35,404.5 5.95,404.89 ; 6.35,404.5 5.95,404.1 ; MH4.7 59.45,305.67 ; MH4.7 58.66,306.47 ; MH4.7 58.66,305.67 ; MH4.7 59.45,306.47 ; 61.68,368.79 J2.B5 ; J2.B5 61.68,369.92 ; J2.B5 62.81,368.79 ; J2.B5 62.81,369.92 ; MH4.6 60.75,303.32 ; MH4.6 60.75,302.52 ; MH4.6 59.95,302.52 ; MH4.6 59.95,303.32 ; 64.18,348.79 J2.A23 ; J2.A23 65.31,348.79 ; J2.A23 64.18,349.92 ; J2.A23 65.31,349.92 ; J2.B18 60.81,354.92 ; J2.B18 59.68,353.79 ; J2.B18 60.81,353.79 ; J2.B18 59.68,354.92 ; 63.1,310.91 MH4.1 ; MH4.1 63.1,310.12 ; MH4.1 63.9,310.91 ; MH4.1 63.9,310.12 ; 61.68,359.92 J2.B13 ; J2.B13 61.68,358.79 ; J2.B13 62.81,358.79 ; J2.B13 62.81,359.92 ; 66.18,368.92 J2.A6 ; J2.A6 66.18,367.79 ; J2.A6 67.31,367.79 ; J2.A6 67.31,368.92 ; MH4.4 67.05,303.32 ; MH4.4 67.05,302.52 ; MH4.4 66.25,302.52 ; MH4.4 66.25,303.32 ; 66.25,88.64 MH6.2 ; MH6.2 67.05,88.64 ; MH6.2 67.05,87.84 ; MH6.2 66.25,87.84 ; 2.8,412.49 MH1.8 ; MH1.8 3.6,411.69 ; MH1.8 2.8,411.69 ; MH1.8 3.6,412.49 ; 66.18,364.92 J2.A10 ; J2.A10 67.31,363.79 ; J2.A10 67.31,364.92 ; J2.A10 66.18,363.79 ; J2.B8 60.81,366.92 ; J2.B8 59.68,365.79 ; J2.B8 59.68,366.92 ; J2.B8 60.81,365.79 ; 66.18,370.92 J2.A4 ; J2.A4 67.31,370.92 ; J2.A4 67.31,369.79 ; J2.A4 66.18,369.79 ; 59.68,342.92 J2.B30 ; J2.B30 60.81,342.92 ; J2.B30 60.81,341.79 ; J2.B30 59.68,341.79 ; 2.8,87.84 MH5.8 ; MH5.8 3.6,87.84 ; MH5.8 3.6,88.64 ; MH5.8 2.8,88.64 ; MH6.3 68.34,85.49 ; MH6.3 67.55,85.49 ; MH6.3 67.55,84.69 ; MH6.3 68.34,84.69 ; 117.1,406.19 MH3.6 ; MH3.6 117.1,405.39 ; MH3.6 117.9,406.19 ; MH3.6 117.9,405.39 ; 9.1,87.84 MH5.2 ; MH5.2 9.1,88.64 ; MH5.2 9.9,88.64 ; MH5.2 9.9,87.84 ; 59.95,82.34 MH6.6 ; MH6.6 59.95,81.54 ; MH6.6 60.75,81.54 ; MH6.6 60.75,82.34 ; 67.55,306.47 MH4.3 ; MH4.3 67.55,305.67 ; MH4.3 68.34,305.67 ; MH4.3 68.34,306.47 ; J2.A12 67.31,360.92 ; J2.A12 66.18,359.79 ; J2.A12 67.31,359.79 ; J2.A12 66.18,360.92 ; 5.95,81.04 MH5.5 ; MH5.5 6.75,80.25 ; MH5.5 6.75,81.04 ; MH5.5 5.95,80.25 ; 124.7,85.49 MH7.3 ; MH7.3 125.49,84.69 ; MH7.3 125.49,85.49 ; MH7.3 124.7,84.69 ; 63.1,301.23 MH4.5 ; MH4.5 63.1,302.02 ; MH4.5 63.9,302.02 ; MH4.5 63.9,301.23 ; J2.B1 62.81,373.92 ; J2.B1 61.68,372.79 ; J2.B1 62.81,372.79 ; J2.B1 61.68,373.92 ; J2.A32 67.31,339.79 ; J2.A32 66.18,340.92 ; J2.A32 66.18,339.79 ; J2.A32 67.31,340.92 ; J2.A8 67.31,366.92 ; J2.A8 66.18,365.79 ; J2.A8 66.18,366.92 ; J2.A8 67.31,365.79 ; MH3.3 125.49,409.34 ; MH3.3 125.49,408.54 ; MH3.3 124.7,409.34 ; MH3.3 124.7,408.54 ; 2.8,406.19 MH1.6 ; MH1.6 2.8,405.39 ; MH1.6 3.6,406.19 ; MH1.6 3.6,405.39 ; MH2.2 67.05,411.69 ; MH2.2 67.05,412.49 ; MH2.2 66.25,411.69 ; MH2.2 66.25,412.49 ; 64.18,368.79 J2.A5 ; J2.A5 65.31,368.79 ; J2.A5 64.18,369.92 ; J2.A5 65.31,369.92 ; 9.1,411.69 MH1.2 ; MH1.2 9.9,412.49 ; MH1.2 9.1,412.49 ; MH1.2 9.9,411.69 ; 117.1,88.64 MH7.8 ; MH7.8 117.1,87.84 ; MH7.8 117.9,88.64 ; MH7.8 117.9,87.84 ; MH2.8 60.75,412.49 ; MH2.8 60.75,411.69 ; MH2.8 59.95,411.69 ; MH2.8 59.95,412.49 ; J2.B17 62.81,355.92 ; J2.B17 61.68,355.92 ; J2.B17 61.68,354.79 ; J2.B17 62.81,354.79 ; MH4.8 60.75,308.82 ; MH4.8 59.95,309.62 ; MH4.8 59.95,308.82 ; MH4.8 60.75,309.62 ; 64.18,371.92 J2.A3 ; J2.A3 64.18,370.79 ; J2.A3 65.31,370.79 ; J2.A3 65.31,371.92 ; MH5.7 2.3,84.69 ; MH5.7 1.51,84.69 ; MH5.7 1.51,85.49 ; MH5.7 2.3,85.49 ; J2.A24 67.31,348.92 ; J2.A24 67.31,347.79 ; J2.A24 66.18,348.92 ; J2.A24 66.18,347.79 ; 59.68,346.92 J2.B26 ; J2.B26 60.81,346.92 ; J2.B26 60.81,345.79 ; J2.B26 59.68,345.79 ; J2.A11 65.31,362.79 ; J2.A11 65.31,363.92 ; J2.A11 64.18,363.92 ; 59.68,369.79 J2.B4 ; J2.B4 60.81,369.79 ; J2.B4 59.68,370.92 ; J2.B4 60.81,370.92 ; MH2.4 67.05,406.19 ; MH2.4 66.25,405.39 ; MH2.4 66.25,406.19 ; MH2.4 67.05,405.39 ; 66.18,371.79 J2.A2 ; J2.A2 67.31,371.79 ; J2.A2 67.31,372.92 ; J2.A2 66.18,372.92 ; 66.25,82.34 MH6.4 ; MH6.4 67.05,81.54 ; MH6.4 67.05,82.34 ; MH6.4 66.25,81.54 ; 10.4,409.34 MH1.3 ; MH1.3 11.19,409.34 ; MH1.3 11.19,408.54 ; MH1.3 10.4,408.54 ; J2.A20 67.31,351.79 ; J2.A20 66.18,352.92 ; J2.A20 66.18,351.79 ; J2.A20 67.31,352.92 ; 63.1,404.89 63.5,404.5 ; 63.5,404.5 63.1,404.1 ; 63.5,404.5 63.9,404.89 ; 63.5,404.5 63.9,404.1 ; 64.18,344.79 J2.A27 ; J2.A27 65.31,345.92 ; J2.A27 64.18,345.92 ; J2.A27 65.31,344.79 ; MH6.8 60.75,88.64 ; MH6.8 59.95,87.84 ; MH6.8 59.95,88.64 ; MH6.8 60.75,87.84 ; 61.68,351.92 J2.B21 ; J2.B21 61.68,350.79 ; J2.B21 62.81,351.92 ; J2.B21 62.81,350.79 ; 59.95,405.39 MH2.6 ; MH2.6 60.75,406.19 ; MH2.6 60.75,405.39 ; MH2.6 59.95,406.19
  LAYER3 w0.254: J2.A28 67.31,344.92 ; J2.A28 67.31,343.79 ; J2.A28 66.18,343.79 ; J2.A28 66.18,344.92 ; MH4.2 67.05,308.82 ; MH4.2 66.25,308.82 ; MH4.2 67.05,309.62 ; MH4.2 66.25,309.62 ; J2.A10 67.31,363.79 ; J2.A10 66.18,364.92 ; J2.A10 66.18,363.79 ; J2.A10 67.31,364.92 ; 61.68,354.79 J2.B17 ; J2.B17 62.81,354.79 ; J2.B17 62.81,355.92 ; J2.B17 61.68,355.92 ; J2.A15 65.31,356.79 ; J2.A15 64.18,356.79 ; J2.A15 64.18,357.92 ; J2.A15 65.31,357.92 ; J2.A5 65.31,369.92 ; J2.A5 64.18,368.79 ; J2.A5 64.18,369.92 ; J2.A5 65.31,368.79 ; MH4.6 60.75,302.52 ; MH4.6 60.75,303.32 ; MH4.6 59.95,303.32 ; MH4.6 59.95,302.52 ; MH4.3 68.34,305.67 ; MH4.3 67.55,305.67 ; MH4.3 68.34,306.47 ; MH4.3 67.55,306.47 ; MH5.3 11.19,85.49 ; MH5.3 10.4,84.69 ; MH5.3 10.4,85.49 ; MH5.3 11.19,84.69 ; MH6.6 60.75,81.54 ; MH6.6 60.75,82.34 ; MH6.6 59.95,81.54 ; MH6.6 59.95,82.34 ; J2.A23 65.31,349.92 ; J2.A23 64.18,348.79 ; J2.A23 65.31,348.79 ; J2.A23 64.18,349.92 ; J2.A14 67.31,357.79 ; J2.A14 66.18,357.79 ; J2.A14 67.31,358.92 ; J2.A14 66.18,358.92 ; MH6.2 67.05,87.84 ; MH6.2 66.25,88.64 ; MH6.2 66.25,87.84 ; MH6.2 67.05,88.64 ; 116.2,408.94 116.6,409.34 ; 116.2,408.94 115.81,408.54 ; 116.2,408.94 115.81,409.34 ; 116.2,408.94 116.6,408.54 ; MH6.5 63.9,80.25 ; MH6.5 63.1,80.25 ; MH6.5 63.9,81.04 ; MH6.5 63.1,81.04 ; 66.18,370.92 J2.A4 ; J2.A4 66.18,369.79 ; J2.A4 67.31,370.92 ; J2.A4 67.31,369.79 ; MH2.7 59.45,409.34 ; MH2.7 59.45,408.54 ; MH2.7 58.66,409.34 ; MH2.7 58.66,408.54 ; 66.18,356.92 J2.A16 ; J2.A16 66.18,355.79 ; J2.A16 67.31,355.79 ; J2.A16 67.31,356.92 ; 61.68,363.92 J2.B11 ; J2.B11 61.68,362.79 ; J2.B11 62.81,363.92 ; 59.68,357.79 J2.B14 ; J2.B14 59.68,358.92 ; J2.B14 60.81,357.79 ; J2.B14 60.81,358.92 ; 61.68,365.92 J2.B9 ; J2.B9 61.68,364.79 ; J2.B9 62.81,365.92 ; J2.B9 62.81,364.79 ; J2.A6 67.31,367.79 ; J2.A6 66.18,367.79 ; J2.A6 67.31,368.92 ; J2.A6 66.18,368.92 ; 5.95,81.04 MH5.5 ; MH5.5 5.95,80.25 ; MH5.5 6.75,80.25 ; MH5.5 6.75,81.04 ; MH6.7 59.45,85.49 ; MH6.7 58.66,85.49 ; MH6.7 59.45,84.69 ; MH6.7 58.66,84.69 ; J2.A2 67.31,372.92 ; J2.A2 67.31,371.79 ; J2.A2 66.18,372.92 ; J2.A2 66.18,371.79 ; MH3.4 124.2,405.39 ; MH3.4 124.2,406.19 ; MH3.4 123.4,405.39 ; MH3.4 123.4,406.19 ; MH3.2 124.2,412.49 ; MH3.2 124.2,411.69 ; MH3.2 123.4,412.49 ; MH3.2 123.4,411.69 ; MH5.2 9.9,88.64 ; MH5.2 9.1,88.64 ; MH5.2 9.1,87.84 ; MH5.2 9.9,87.84 ; J2.A24 67.31,347.79 ; J2.A24 66.18,347.79 ; J2.A24 67.31,348.92 ; J2.A24 66.18,348.92 ; 9.1,405.39 MH1.4 ; MH1.4 9.9,406.19 ; MH1.4 9.9,405.39 ; MH1.4 9.1,406.19 ; MH2.8 60.75,411.69 ; MH2.8 59.95,412.49 ; MH2.8 60.75,412.49 ; MH2.8 59.95,411.69 ; 64.18,373.92 J2.A1 ; J2.A1 65.31,373.92 ; J2.A1 64.18,372.79 ; J2.A1 65.31,372.79 ; 61.68,350.79 J2.B21 ; J2.B21 62.81,351.92 ; J2.B21 62.81,350.79 ; J2.B21 61.68,351.92 ; J2.B22 60.81,350.92 ; J2.B22 59.68,349.79 ; J2.B22 59.68,350.92 ; J2.B22 60.81,349.79 ; 63.1,412.99 MH2.1 ; MH2.1 63.9,412.99 ; MH2.1 63.1,413.78 ; MH2.1 63.9,413.78 ; MH7.8 117.9,88.64 ; MH7.8 117.1,88.64 ; MH7.8 117.9,87.84 ; MH7.8 117.1,87.84 ; MH4.1 63.9,310.91 ; MH4.1 63.1,310.12 ; MH4.1 63.9,310.12 ; MH4.1 63.1,310.91 ; 9.1,412.49 MH1.2 ; MH1.2 9.1,411.69 ; MH1.2 9.9,412.49 ; MH1.2 9.9,411.69 ; MH4.4 67.05,302.52 ; MH4.4 66.25,303.32 ; MH4.4 67.05,303.32 ; MH4.4 66.25,302.52 ; 59.68,341.79 J2.B30 ; J2.B30 60.81,342.92 ; J2.B30 59.68,342.92 ; J2.B30 60.81,341.79 ; J2.B26 60.81,345.79 ; J2.B26 59.68,345.79 ; J2.B26 59.68,346.92 ; J2.B26 60.81,346.92 ; J2.A32 67.31,340.92 ; J2.A32 67.31,339.79 ; J2.A32 66.18,339.79 ; J2.A32 66.18,340.92 ; 124.7,85.49 MH7.3 ; MH7.3 125.49,84.69 ; MH7.3 125.49,85.49 ; MH7.3 124.7,84.69 ; J2.B3 62.81,371.92 ; J2.B3 62.81,370.79 ; J2.B3 61.68,370.79 ; J2.B3 61.68,371.92 ; 67.55,408.54 MH2.3 ; MH2.3 67.55,409.34 ; MH2.3 68.34,409.34 ; MH2.3 68.34,408.54 ; 64.18,358.79 J2.A13 ; J2.A13 65.31,358.79 ; J2.A13 65.31,359.92 ; J2.A13 64.18,359.92 ; 64.18,344.79 J2.A27 ; J2.A27 65.31,345.92 ; J2.A27 65.31,344.79 ; J2.A27 64.18,345.92 ; 61.68,369.92 J2.B5 ; J2.B5 62.81,368.79 ; J2.B5 62.81,369.92 ; J2.B5 61.68,368.79 ; J2.B29 62.81,343.92 ; J2.B29 61.68,342.79 ; J2.B29 62.81,342.79 ; J2.B29 61.68,343.92 ; 61.68,372.79 J2.B1 ; J2.B1 61.68,373.92 ; J2.B1 62.81,373.92 ; J2.B1 62.81,372.79 ; 66.25,411.69 MH2.2 ; MH2.2 66.25,412.49 ; MH2.2 67.05,412.49 ; MH2.2 67.05,411.69 ; J2.B10 60.81,363.79 ; J2.B10 59.68,363.79 ; J2.B10 60.81,364.92 ; J2.B10 59.68,364.92 ; 64.18,371.92 J2.A3 ; J2.A3 65.31,371.92 ; J2.A3 64.18,370.79 ; J2.A3 65.31,370.79 ; 59.68,368.92 J2.B6 ; J2.B6 60.81,367.79 ; J2.B6 59.68,367.79 ; J2.B6 60.81,368.92 ; 59.68,353.79 J2.B18 ; J2.B18 59.68,354.92 ; J2.B18 60.81,353.79 ; J2.B18 60.81,354.92 ; 64.18,341.92 J2.A31 ; J2.A31 65.31,340.79 ; J2.A31 65.31,341.92 ; J2.A31 64.18,340.79 ; 59.68,360.92 J2.B12 ; J2.B12 60.81,359.79 ; J2.B12 59.68,359.79 ; J2.B12 60.81,360.92 ; MH6.3 68.34,84.69 ; MH6.3 68.34,85.49 ; MH6.3 67.55,85.49 ; MH6.3 67.55,84.69 ; 115.81,84.69 116.2,85.09 ; 116.2,85.09 116.6,84.69 ; 116.2,85.09 115.81,85.49 ; 116.2,85.09 116.6,85.49 ; 5.95,412.99 MH1.1 ; MH1.1 6.75,412.99 ; MH1.1 5.95,413.78 ; MH1.1 6.75,413.78 ; J2.A19 65.31,353.92 ; J2.A19 64.18,353.92 ; J2.A19 64.18,352.79 ; J2.A19 65.31,352.79 ; 58.66,305.67 MH4.7 ; MH4.7 59.45,305.67 ; MH4.7 58.66,306.47 ; MH4.7 59.45,306.47 ; J2.B8 60.81,366.92 ; J2.B8 59.68,365.79 ; J2.B8 59.68,366.92 ; J2.B8 60.81,365.79 ; 9.1,82.34 MH5.4 ; MH5.4 9.9,81.54 ; MH5.4 9.1,81.54 ; MH5.4 9.9,82.34 ; 124.7,409.34 MH3.3 ; MH3.3 125.49,408.54 ; MH3.3 124.7,408.54 ; MH3.3 125.49,409.34 ; 66.18,352.92 J2.A20 ; J2.A20 67.31,352.92 ; J2.A20 67.31,351.79 ; J2.A20 66.18,351.79 ; 63.5,404.5 63.9,404.89 ; 63.5,404.5 63.1,404.1 ; 63.5,404.5 63.9,404.1 ; 63.5,404.5 63.1,404.89 ; MH7.6 117.9,82.34 ; MH7.6 117.1,81.54 ; MH7.6 117.1,82.34 ; MH7.6 117.9,81.54 ; 61.68,347.92 J2.B25 ; J2.B25 61.68,346.79 ; J2.B25 62.81,347.92 ; J2.B25 62.81,346.79 ; 64.18,366.79 J2.A7 ; J2.A7 65.31,367.92 ; J2.A7 65.31,366.79 ; J2.A7 64.18,367.92 ; 66.25,406.19 MH2.4 ; MH2.4 66.25,405.39 ; MH2.4 67.05,405.39 ; MH2.4 67.05,406.19 ; MH3.6 117.9,405.39 ; MH3.6 117.9,406.19 ; MH3.6 117.1,406.19 ; MH3.6 117.1,405.39 ; 1.51,409.34 MH1.7 ; MH1.7 1.51,408.54 ; MH1.7 2.3,409.34 ; MH1.7 2.3,408.54 ; MH4.8 60.75,308.82 ; MH4.8 59.95,308.82 ; MH4.8 60.75,309.62 ; MH4.8 59.95,309.62 ; MH1.6 3.6,406.19 ; MH1.6 3.6,405.39 ; MH1.6 2.8,406.19 ; MH1.6 2.8,405.39 ; MH3.1 121.05,413.78 ; MH3.1 120.25,412.99 ; MH3.1 121.05,412.99 ; MH3.1 120.25,413.78 ; MH7.4 124.2,82.34 ; MH7.4 123.4,82.34 ; MH7.4 124.2,81.54 ; MH7.4 123.4,81.54 ; 63.1,89.93 MH6.1 ; MH6.1 63.9,89.14 ; MH6.1 63.9,89.93 ; MH6.1 63.1,89.14 ; 66.25,82.34 MH6.4 ; MH6.4 67.05,82.34 ; MH6.4 67.05,81.54 ; MH6.4 66.25,81.54 ; 59.95,406.19 MH2.6 ; MH2.6 60.75,406.19 ; MH2.6 60.75,405.39 ; MH2.6 59.95,405.39 ; MH5.7 2.3,85.49 ; MH5.7 2.3,84.69 ; MH5.7 1.51,85.49 ; MH5.7 1.51,84.69 ; 120.25,404.1 120.65,404.5 ; 120.65,404.5 120.25,404.89 ; 120.65,404.5 121.05,404.89 ; 120.65,404.5 121.05,404.1 ; MH4.5 63.9,301.23 ; MH4.5 63.9,302.02 ; MH4.5 63.1,302.02 ; MH4.5 63.1,301.23 ; J2.A12 67.31,359.79 ; J2.A12 66.18,359.79 ; J2.A12 66.18,360.92 ; J2.A12 67.31,360.92 ; 5.95,404.89 6.35,404.5 ; 6.35,404.5 6.75,404.89 ; 6.35,404.5 5.95,404.1 ; 6.35,404.5 6.75,404.1 ; 2.8,82.34 MH5.6 ; MH5.6 3.6,82.34 ; MH5.6 2.8,81.54 ; MH5.6 3.6,81.54 ; MH5.8 3.6,88.64 ; MH5.8 2.8,87.84 ; MH5.8 2.8,88.64 ; MH5.8 3.6,87.84 ; MH1.3 11.19,409.34 ; MH1.3 10.4,409.34 ; MH1.3 11.19,408.54 ; MH1.3 10.4,408.54 ; J2.B2 60.81,372.92 ; J2.B2 60.81,371.79 ; J2.B2 59.68,372.92 ; J2.B2 59.68,371.79 ; 120.25,89.93 MH7.1 ; MH7.1 121.05,89.14 ; MH7.1 121.05,89.93 ; MH7.1 120.25,89.14 ; 59.95,88.64 MH6.8 ; MH6.8 59.95,87.84 ; MH6.8 60.75,87.84 ; MH6.8 60.75,88.64 ; J2.A11 65.31,363.92 ; J2.A11 65.31,362.79 ; J2.A11 64.18,363.92 ; J2.B7 62.81,367.92 ; J2.B7 61.68,366.79 ; J2.B7 61.68,367.92 ; J2.B7 62.81,366.79 ; MH3.8 117.9,411.69 ; MH3.8 117.1,412.49 ; MH3.8 117.1,411.69 ; MH3.8 117.9,412.49 ; 120.25,80.25 MH7.5 ; MH7.5 121.05,81.04 ; MH7.5 121.05,80.25 ; MH7.5 120.25,81.04 ; J2.A8 67.31,366.92 ; J2.A8 66.18,366.92 ; J2.A8 67.31,365.79 ; J2.A8 66.18,365.79 ; J2.B4 60.81,369.79 ; J2.B4 60.81,370.92 ; J2.B4 59.68,370.92 ; J2.B4 59.68,369.79 ; 123.4,87.84 MH7.2 ; MH7.2 124.2,87.84 ; MH7.2 123.4,88.64 ; MH7.2 124.2,88.64 ; MH1.8 3.6,411.69 ; MH1.8 2.8,411.69 ; MH1.8 3.6,412.49 ; MH1.8 2.8,412.49 ; J2.B13 62.81,358.79 ; J2.B13 62.81,359.92 ; J2.B13 61.68,358.79 ; J2.B13 61.68,359.92 ; 5.95,89.93 MH5.1 ; MH5.1 6.75,89.93 ; MH5.1 6.75,89.14 ; MH5.1 5.95,89.14 ; 64.18,364.79 J2.A9 ; J2.A9 65.31,364.79 ; J2.A9 65.31,365.92 ; J2.A9 64.18,365.92
  BOTTOM w0.184: 64.33,7.9 64.55,7.68 v1(64.55,7.19)
  BOTTOM w0.254: 66.18,360.92 J2.A12 ; J2.A12 67.31,359.79 ; J2.A12 66.18,359.79 ; J2.A12 67.31,360.92 ; 61.68,368.79 J2.B5 ; J2.B5 62.81,368.79 ; J2.B5 61.68,369.92 ; J2.B5 62.81,369.92 ; J2.B2 60.81,372.92 ; J2.B2 60.81,371.79 ; J2.B2 59.68,372.92 ; J2.B2 59.68,371.79 ; J2.B29 62.81,343.92 ; J2.B29 61.68,342.79 ; J2.B29 61.68,343.92 ; J2.B29 62.81,342.79 ; J2.A7 65.31,366.79 ; J2.A7 65.31,367.92 ; J2.A7 64.18,367.92 ; J2.A7 64.18,366.79 ; J2.B13 62.81,358.79 ; J2.B13 62.81,359.92 ; J2.B13 61.68,359.92 ; J2.B13 61.68,358.79 ; 64.18,358.79 J2.A13 ; J2.A13 64.18,359.92 ; J2.A13 65.31,358.79 ; J2.A13 65.31,359.92 ; 64.18,365.92 J2.A9 ; J2.A9 65.31,364.79 ; J2.A9 64.18,364.79 ; J2.A9 65.31,365.92 ; 66.18,344.92 J2.A28 ; J2.A28 67.31,344.92 ; J2.A28 67.31,343.79 ; J2.A28 66.18,343.79 ; 61.68,362.79 J2.B11 ; J2.B11 62.81,363.92 ; J2.B11 61.68,363.92 ; 66.18,367.79 J2.A6 ; J2.A6 67.31,367.79 ; J2.A6 66.18,368.92 ; J2.A6 67.31,368.92 ; 64.18,371.92 J2.A3 ; J2.A3 64.18,370.79 ; J2.A3 65.31,370.79 ; J2.A3 65.31,371.92 ; J2.B18 60.81,353.79 ; J2.B18 60.81,354.92 ; J2.B18 59.68,353.79 ; J2.B18 59.68,354.92 ; 64.18,344.79 J2.A27 ; J2.A27 64.18,345.92 ; J2.A27 65.31,345.92 ; J2.A27 65.31,344.79 ; 64.02,372.63 J2.A1 ; J2.A1 64.02,374.08 ; J2.A1 65.47,372.63 ; J2.A1 65.47,374.08 ; J2.B9 62.81,364.79 ; J2.B9 61.68,364.79 ; J2.B9 62.81,365.92 ; J2.B9 61.68,365.92 ; 59.68,366.92 J2.B8 ; J2.B8 60.81,366.92 ; J2.B8 59.68,365.79 ; J2.B8 60.81,365.79 ; J2.A8 67.31,366.92 ; J2.A8 66.18,365.79 ; J2.A8 67.31,365.79 ; J2.A8 66.18,366.92 ; 61.68,346.79 J2.B25 ; J2.B25 62.81,346.79 ; J2.B25 61.68,347.92 ; J2.B25 62.81,347.92 ; J2.A32 67.31,339.79 ; J2.A32 67.31,340.92 ; J2.A32 66.18,339.79 ; J2.A32 66.18,340.92 ; J2.A16 67.31,356.92 ; J2.A16 66.18,355.79 ; J2.A16 67.31,355.79 ; J2.A16 66.18,356.92 ; J2.A11 65.31,362.79 ; J2.A11 64.18,363.92 ; J2.A11 65.31,363.92 ; 64.18,349.92 J2.A23 ; J2.A23 64.18,348.79 ; J2.A23 65.31,349.92 ; J2.A23 65.31,348.79 ; 59.68,360.92 J2.B12 ; J2.B12 60.81,360.92 ; J2.B12 60.81,359.79 ; J2.B12 59.68,359.79 ; J2.A15 65.31,357.92 ; J2.A15 64.18,356.79 ; J2.A15 65.31,356.79 ; J2.A15 64.18,357.92 ; 64.18,369.92 J2.A5 ; J2.A5 64.18,368.79 ; J2.A5 65.31,368.79 ; J2.A5 65.31,369.92 ; J2.A10 67.31,363.79 ; J2.A10 66.18,364.92 ; J2.A10 66.18,363.79 ; J2.A10 67.31,364.92 ; J2.A19 65.31,353.92 ; J2.A19 65.31,352.79 ; J2.A19 64.18,352.79 ; J2.A19 64.18,353.92 ; J2.B3 62.81,370.79 ; J2.B3 61.68,370.79 ; J2.B3 61.68,371.92 ; J2.B3 62.81,371.92 ; J2.B10 60.81,363.79 ; J2.B10 59.68,363.79 ; J2.B10 59.68,364.92 ; J2.B10 60.81,364.92 ; 66.18,371.79 J2.A2 ; J2.A2 66.18,372.92 ; J2.A2 67.31,372.92 ; J2.A2 67.31,371.79 ; J2.B6 60.81,368.92 ; J2.B6 59.68,367.79 ; J2.B6 60.81,367.79 ; J2.B6 59.68,368.92 ; J2.B14 60.81,358.92 ; J2.B14 59.68,358.92 ; J2.B14 60.81,357.79 ; J2.B14 59.68,357.79 ; J2.A24 67.31,347.79 ; J2.A24 66.18,347.79 ; J2.A24 67.31,348.92 ; J2.A24 66.18,348.92 ; J2.B7 62.81,367.92 ; J2.B7 61.68,367.92 ; J2.B7 61.68,366.79 ; J2.B7 62.81,366.79 ; 59.68,349.79 J2.B22 ; J2.B22 60.81,350.92 ; J2.B22 60.81,349.79 ; J2.B22 59.68,350.92 ; 64.18,340.79 J2.A31 ; J2.A31 64.18,341.92 ; J2.A31 65.31,341.92 ; J2.A31 65.31,340.79 ; 59.68,342.92 J2.B30 ; J2.B30 60.81,342.92 ; J2.B30 60.81,341.79 ; J2.B30 59.68,341.79 ; J2.A4 67.31,370.92 ; J2.A4 66.18,369.79 ; J2.A4 67.31,369.79 ; J2.A4 66.18,370.92 ; J2.B17 62.81,355.92 ; J2.B17 62.81,354.79 ; J2.B17 61.68,355.92 ; J2.B17 61.68,354.79 ; J2.B26 60.81,345.79 ; J2.B26 60.81,346.92 ; J2.B26 59.68,346.92 ; J2.B26 59.68,345.79 ; 66.18,351.79 J2.A20 ; J2.A20 66.18,352.92 ; J2.A20 67.31,352.92 ; J2.A20 67.31,351.79 ; J2.B1 62.81,372.79 ; J2.B1 62.81,373.92 ; J2.B1 61.68,373.92 ; J2.B1 61.68,372.79 ; J2.B21 62.81,350.79 ; J2.B21 61.68,351.92 ; J2.B21 62.81,351.92 ; J2.B21 61.68,350.79 ; 66.18,358.92 J2.A14 ; J2.A14 67.31,358.92 ; J2.A14 66.18,357.79 ; J2.A14 67.31,357.79 ; 59.68,369.79 J2.B4 ; J2.B4 60.81,370.92 ; J2.B4 59.68,370.92 ; J2.B4 60.81,369.79
  BOTTOM w0.711: J7.A32 75.05,5.91 ; J7.A31 74.05,5.91 ; J7.A9 50.05,6.71 50.52,7.19 ; v1(48.54,7.19) 48.54,7.26 ; 48.54,7.26 48.05,6.77 J7.A7 ; 48.54,7.26 49.05,6.76 J7.A8 ; J7.A16 59.05,5.96 ; J7.A12 55.05,6.03 ; v1(44.55,7.19) 44.55,7.24 ; 44.55,7.24 45.05,6.74 J7.A4 ; 44.55,7.24 44.05,6.73 J7.A3 ; v1(46.56,7.19) 46.05,6.68 J7.A5 ; v1(46.56,7.19) 46.51,7.24 ; v1(46.56,7.19) 47.05,6.7 J7.A6 ; 42.62,7.09 42.05,6.51 J7.A1 ; 42.62,7.09 v1(42.53,7.19) ; 42.62,7.09 43.05,6.66 J7.A2 ; J7.A23 66.05,6.03 ; 50.52,7.19 51.05,6.66 J7.A10 ; 50.52,7.19 v1(50.55,7.19) ; J7.A20 63.05,6.03 ; v1(52.05,7.19) J7.A11 ; J7.A28 71.05,5.91 ; J7.A27 70.05,6.03 ; J7.A24 67.05,6.03 ; J7.A15 58.05,6.03 ; J7.A14 57.05,6.03 ; J7.A13 56.05,6.03 ; J7.A19 62.05,6.03
  vias: v1(18.6,348.13) v1(18.6,346.32) v1(20.5,190.17) v1(20.5,188.36) v1(20.48,134.73) v1(20.5,348.13) v1(20.5,346.32) v1(20.52,266.34) v1(20.52,264.54) v1(20.5,155.59) v1(20.5,153.78) v1(20.5,136.51) v1(22.38,134.73) v1(22.41,348.13) v1(22.41,346.32) v1(22.43,266.34) v1(22.43,264.54) v1(22.41,228.26) v1(22.41,226.45) v1(22.4,190.17) v1(22.4,188.36) v1(22.41,155.59) v1(22.41,153.78) v1(22.41,136.51) v1(22.69,247.31) v1(22.64,245.53) v1(24.28,188.32) v1(24.31,348.13) v1(24.31,346.32) v1(24.33,266.34) v1(24.33,264.54) v1(24.31,228.26) v1(24.31,226.45) v1(24.31,209.19) v1(24.31,207.41) v1(24.34,190.14) v1(24.32,155.59) v1(24.31,153.78) v1(24.33,136.53) v1(24.33,134.67) v1(24.47,247.31) v1(24.41,245.53) v1(25.13,329.66) v1(25.19,327.8) v1(25.44,187.46) v1(25.59,185.69) v1(25.59,183.78) v1(25.59,181.88) v1(25.59,179.97) v1(25.59,178.1) v1(26.19,245.53) v1(26.22,348.13) v1(26.22,346.32) v1(26.24,266.34) v1(26.24,264.54) v1(26.24,247.31) v1(26.24,227.95) v1(26.2,225.65) v1(26.22,209.19) v1(26.22,207.41) v1(26.22,189.36) v1(26.28,176.64) v1(26.22,155.59) v1(26.21,153.78) v1(26.26,136.41) v1(26.41,223.76) v1(26.59,221.85) v1(26.63,134.18) v1(26.74,329.68) v1(27.06,132.37) v1(27.13,327.84) v1(27.25,187.67) v1(27.38,185.64) v1(27.38,183.74) v1(27.38,181.83) v1(27.38,179.93) v1(27.46,226.97) v1(27.45,220.53) v1(27.87,135.52) v1(28.02,330.14) v1(28.1,245.53) v1(28.12,348.13) v1(28.12,346.32) v1(28.14,266.34) v1(28.14,264.54) v1(28.15,247.31) v1(28.12,225.64) v1(28.12,209.19) v1(28.12,207.41) v1(28.13,177.86) v1(28.13,176.03) v1(28.13,155.59) v1(28.12,153.78) v1(28.1,130.62) v1(28.12,15.53) v1(28.13,13.75) v1(28.23,223.76) v1(28.31,222.38) v1(28.63,134.3) v1(28.78,328.45) v1(28.86,132.44) v1(29.06,219.62) v1(29.19,221.46) v1(29.99,348.18) v1(29.98,330.96) v1(29.96,129.43) v1(30.05,346.34) v1(30.05,266.34) v1(30.05,264.54) v1(30.05,247.31) v1(30,245.53) v1(30.03,209.19) v1(30.03,207.41) v1(30.04,177.86) v1(30.04,176.03) v1(30.03,155.59) v1(30.02,153.78) v1(30.05,131.33) v1(30.03,15.53) v1(30.04,13.75) v1(30.12,329.01) v1(30.93,221.31) v1(30.93,219.51) v1(31.9,348.82) v1(31.81,332.27) v1(31.95,266.34) v1(31.95,264.54) v1(31.96,247.31) v1(31.91,245.53) v1(31.93,209.19) v1(31.93,207.41) v1(31.94,177.86) v1(31.94,176.03) v1(31.94,155.59) v1(31.93,153.78) v1(31.92,131.21) v1(31.94,129.36) v1(31.93,15.53) v1(31.94,13.75) v1(32,346.97) v1(32.05,330.09) v1(32.71,221.31) v1(32.71,219.51) v1(33.73,333.81) v1(33.82,380.42) v1(33.84,378.64) v1(33.86,360.32) v1(33.88,358.43) v1(33.82,349.25) v1(33.82,347.46) v1(33.86,266.34) v1(33.86,264.54) v1(33.86,247.31) v1(33.81,245.53) v1(33.84,209.19) v1(33.84,207.41) v1(33.85,177.86) v1(33.85,176.03) v1(33.84,155.59) v1(33.83,153.78) v1(33.83,131.21) v1(33.84,129.36) v1(33.84,15.53) v1(33.85,13.75) v1(33.95,331.63) v1(34.49,221.31) v1(34.49,219.51) v1(34.97,27.59) v1(35.16,25.57) v1(35.61,335.31) v1(35.72,380.42) v1(35.74,378.64) v1(35.76,360.32) v1(35.78,358.43) v1(35.73,349.25) v1(35.73,347.46) v1(35.76,266.34) v1(35.76,264.54) v1(35.77,247.31) v1(35.72,245.53) v1(35.74,209.19) v1(35.74,207.41) v1(35.75,177.86) v1(35.75,176.03) v1(35.75,155.59) v1(35.74,153.78) v1(35.73,131.21) v1(35.75,129.36) v1(35.74,15.53) v1(35.75,13.75) v1(35.92,333.22) v1(36.27,221.31) v1(36.27,219.51) v1(36.23,23.99) v1(36.62,377.44) v1(36.69,362.94) v1(36.81,27.58) v1(36.87,26.1) v1(36.84,16.65) v1(37.13,336.58) v1(37.25,322.87) v1(37.25,320.97) v1(37.38,376.03) v1(37.44,324.75) v1(37.45,14.14) v1(37.56,363.98) v1(37.52,358.91) v1(37.51,22.7) v1(37.66,379.3) v1(37.63,349.25) v1(37.63,347.46) v1(37.67,266.34) v1(37.67,264.54) v1(37.67,247.31) v1(37.62,245.53) v1(37.65,209.19) v1(37.65,207.41) v1(37.66,177.86) v1(37.66,176.03) v1(37.65,155.59) v1(37.64,153.78) v1(37.64,131.21) v1(37.65,129.36) v1(37.74,334.7) v1(37.87,24.89) v1(38.04,221.31) v1(38.04,219.51) v1(38.28,374.36) v1(38.3,360.45) v1(38.4,326.16) v1(38.43,362.27) v1(38.42,17.03) v1(38.47,15.23) v1(38.65,337.74) v1(38.86,377.1) v1(39.05,322.85) v1(39.05,320.95) v1(39.37,372.36) v1(39.31,364.26) v1(39.47,20.75) v1(39.49,14.1) v1(39.54,349.25) v1(39.54,347.46) v1(39.55,336.12) v1(39.57,266.34) v1(39.57,264.54) v1(39.58,247.31) v1(39.53,245.53) v1(39.55,209.19) v1(39.55,207.41) v1(39.56,177.86) v1(39.56,176.03) v1(39.56,155.59) v1(39.55,153.78) v1(39.54,131.21) v1(39.56,129.36) v1(39.62,324.86) v1(39.76,375.42) v1(39.79,22.94) v1(39.82,221.31) v1(39.82,219.51) v1(39.95,326.96) v1(40.06,338.89) v1(40.02,16.84) v1(40.44,370.34) v1(40.66,361.96) v1(40.74,15.48) v1(40.96,360.58) v1(41,359.02) v1(41,357.11) v1(41,355.21) v1(41,353.3) v1(41.02,337.34) v1(41.27,372.65) v1(41.32,18.88) v1(41.44,368.44) v1(41.44,349.25) v1(41.44,347.46) v1(41.47,327.03) v1(41.46,325.24) v1(41.48,266.34) v1(41.48,264.54) v1(41.48,247.31) v1(41.43,245.53) v1(41.46,209.19) v1(41.46,207.41) v1(41.47,177.86) v1(41.47,176.03) v1(41.44,155.69) v1(41.47,153.82) v1(41.45,131.21) v1(41.46,129.36) v1(41.45,13.65) v1(41.54,363.65) v1(41.6,221.31) v1(41.6,219.51) v1(41.63,21.13) v1(41.7,340.22) v1(41.88,351.31) v1(42.36,370.63) v1(42.34,15.46) v1(42.5,338.54) v1(42.48,159.03) v1(42.48,157.14) v1(42.51,366.5) v1(42.78,359.04) v1(42.78,357.13) v1(42.78,355.23) v1(42.78,353.32) v1(42.82,360.99) v1(42.82,161) v1(43.3,38.17) v1(43.3,36.27) v1(43.3,34.36) v1(43.3,32.46) v1(43.3,30.55) v1(43.31,350.07) v1(43.35,349.25) v1(43.35,347.46) v1(43.31,341.52) v1(43.38,327.03) v1(43.37,325.24) v1(43.38,266.34) v1(43.38,264.54) v1(43.39,247.31) v1(43.34,245.53) v1(43.38,221.31) v1(43.38,219.51) v1(43.36,209.19) v1(43.36,207.41) v1(43.35,178.16) v1(43.35,131.21) v1(43.37,129.36) v1(43.34,17.48) v1(43.36,13.65) v1(43.41,368.68) v1(43.41,187.64) v1(43.41,185.73) v1(43.41,183.83) v1(43.41,181.92) v1(43.41,180.02) v1(43.42,176.06) v1(43.42,19.42) v1(43.53,364.62) v1(43.57,155.11) v1(43.64,352.15) v1(43.76,339.54) v1(43.83,29.11) v1(43.96,189.56) v1(43.95,162.25) v1(44.29,159) v1(44.27,157.06) v1(44.24,15.46) v1(44.39,366.78) v1(44.53,362.74) v1(44.51,160.31) v1(44.63,342.58) v1(44.61,176.75) v1(45.08,38.2) v1(45.08,36.29) v1(45.08,34.39) v1(45.08,32.48) v1(45.08,30.58) v1(45.19,360.92) v1(45.1,221.97) v1(45.18,219.77) v1(45.19,187.59) v1(45.19,185.68) v1(45.19,183.78) v1(45.19,181.87) v1(45.19,179.97) v1(45.18,177.99) v1(45.12,27.97) v1(45.25,347.46) v1(45.29,340.75) v1(45.28,327.03) v1(45.27,325.24) v1(45.29,266.34) v1(45.29,264.54) v1(45.29,247.31) v1(45.24,245.53) v1(45.28,223.77) v1(45.27,209.19) v1(45.27,207.41) v1(45.27,190.73) v1(45.22,162.73) v1(45.26,131.21) v1(45.27,129.36) v1(45.28,19.17) v1(45.28,17.37) v1(45.26,13.65) v1(45.3,351.35) v1(45.32,349.49) v1(45.33,160.91) v1(45.41,364.94) v1(45.46,359) v1(45.46,225.73) v1(45.88,189) v1(45.85,29.62) v1(45.92,343.75) v1(46.15,15.46) v1(46.34,220.62) v1(46.48,362.92) v1(46.44,227.21) v1(46.62,327.77) v1(46.75,325.61) v1(46.97,360.92) v1(46.92,342.13) v1(47.03,357.03) v1(47.07,223.79) v1(47.06,222.18) v1(47.16,347.46) v1(47.19,266.34) v1(47.19,264.54) v1(47.2,247.31) v1(47.15,245.53) v1(47.17,209.19) v1(47.17,207.41) v1(47.15,191.09) v1(47.18,189.31) v1(47.18,162.78) v1(47.15,160.97) v1(47.16,131.21) v1(47.18,129.36) v1(47.19,29.32) v1(47.17,27.5) v1(47.18,19.17) v1(47.18,17.37) v1(47.17,13.65) v1(47.21,351.35) v1(47.23,349.49) v1(47.24,225.34) v1(47.38,385.71) v1(47.38,383.81) v1(47.38,381.9) v1(47.38,380) v1(47.34,372.33) v1(47.33,328.65) v1(47.42,359.21) v1(47.46,340.45) v1(47.46,338.08) v1(47.46,336.17) v1(47.46,334.27) v1(47.46,332.36) v1(47.46,330.46) v1(47.67,341.66) v1(47.7,374.38) v1(47.89,326.5) v1(48.04,344.87) v1(48.05,15.46) v1(48.11,228.01) v1(48.28,370.38) v1(48.21,226.15) v1(48.44,343.02) v1(48.52,377.78) v1(48.6,376.15) v1(48.76,327.52) v1(48.91,355.13) v1(48.93,26.24) v1(49.06,347.46) v1(49.1,266.34) v1(49.1,264.54) v1(49.05,245.53) v1(49.08,209.19) v1(49.08,207.41) v1(49.06,191.09) v1(49.09,189.31) v1(49.09,162.78) v1(49.06,160.97) v1(49.07,131.21) v1(49.08,129.36) v1(49.09,19.17) v1(49.09,17.37) v1(49.07,13.65) v1(49.16,385.7) v1(49.16,383.79) v1(49.16,381.89) v1(49.16,379.98) v1(49.16,372.41) v1(49.11,351.35) v1(49.13,349.49) v1(49.15,328.45) v1(49.1,247.31) v1(49.12,28.51) v1(49.28,357.3) v1(49.22,340.08) v1(49.26,338.07) v1(49.26,336.17) v1(49.26,334.26) v1(49.26,332.36) v1(49.26,330.45) v1(49.67,341.6) v1(49.82,374.11) v1(49.84,228.01) v1(49.81,226.21) v1(49.96,15.46) v1(50,345.72) v1(50.16,378.58) v1(50.21,368.43) v1(50.22,343.92) v1(50.4,376.18) v1(50.6,370.65) v1(50.65,366.68) v1(50.65,364.77) v1(50.65,362.87) v1(50.65,360.96) v1(50.65,359.06) v1(50.65,357.15) v1(50.83,353.21) v1(50.86,24.31) v1(50.97,347.46) v1(50.96,245.53) v1(50.98,209.19) v1(50.98,207.41) v1(50.96,191.09) v1(50.99,189.31) v1(50.99,162.78) v1(50.96,160.97) v1(50.97,131.21) v1(50.99,129.36) v1(50.99,19.17) v1(50.99,17.37) v1(50.98,13.65) v1(51.03,355.54) v1(51.02,351.35) v1(51.04,349.49) v1(51,266.34) v1(51,264.54) v1(51.01,247.31) v1(51.05,26.61) v1(51.59,226.21) v1(51.62,228.01) v1(51.86,15.46) v1(51.93,346.11) v1(52.15,368.65) v1(52.16,344.3) v1(52.16,342.15) v1(52.45,366.66) v1(52.45,364.75) v1(52.45,362.85) v1(52.45,360.94) v1(52.45,359.04) v1(52.45,357.13) v1(52.76,351.64) v1(52.77,22.41) v1(52.84,354.67) v1(52.87,347.46) v1(52.86,245.53) v1(52.89,209.19) v1(52.89,207.41) v1(52.87,191.09) v1(52.9,189.31) v1(52.9,162.78) v1(52.87,160.97) v1(52.88,131.21) v1(52.89,129.36) v1(52.9,19.17) v1(52.9,17.37) v1(52.88,13.65) v1(52.9,349.51) v1(52.91,266.34) v1(52.91,264.54) v1(52.91,247.31) v1(53,24.68) v1(53.19,353.49) v1(53.4,228.01) v1(53.37,226.21) v1(53.74,346.25) v1(53.75,344.46) v1(53.77,15.46) v1(54.01,21.12) v1(54.76,354.64) v1(54.77,351.47) v1(54.78,347.46) v1(54.78,343.89) v1(54.79,342.09) v1(54.77,245.53) v1(54.79,209.19) v1(54.79,207.41) v1(54.77,191.09) v1(54.77,160.97) v1(54.78,131.21) v1(54.8,129.36) v1(54.76,40.92) v1(54.76,39.02) v1(54.76,37.11) v1(54.76,35.21) v1(54.76,33.3) v1(54.76,31.4) v1(54.76,29.49) v1(54.76,27.59) v1(54.76,25.68) v1(54.79,13.65) v1(54.83,353.28) v1(54.83,349.49) v1(54.81,266.34) v1(54.81,264.54) v1(54.82,247.31) v1(54.8,189.31) v1(54.8,162.78) v1(54.84,23.73) v1(54.8,19.17) v1(54.8,17.37) v1(55.17,228.01) v1(55.14,226.21) v1(55.55,22.54) v1(55.68,346.27) v1(55.66,344.46) v1(55.67,15.46) v1(55.73,19.42) v1(56.21,13.5) v1(56.54,40.94) v1(56.54,39.04) v1(56.54,37.13) v1(56.54,35.23) v1(56.54,33.32) v1(56.54,31.42) v1(56.54,29.51) v1(56.54,27.61) v1(56.54,25.7) v1(56.52,7.19) v1(56.61,354.44) v1(56.68,347.46) v1(56.69,343.89) v1(56.67,245.53) v1(56.7,209.19) v1(56.7,207.41) v1(56.68,191.09) v1(56.68,160.97) v1(56.66,131.41) v1(56.67,21.93) v1(56.73,353.26) v1(56.72,351.45) v1(56.71,349.49) v1(56.72,266.34) v1(56.72,264.54) v1(56.72,247.31) v1(56.71,189.31) v1(56.71,162.78) v1(56.78,129.5) v1(56.71,23.97) v1(56.71,17.37) v1(56.95,228.01) v1(56.92,226.21) v1(56.99,15.12) v1(57.11,20.6) v1(57.25,12.62) v1(57.45,134.23) v1(57.4,132.39) v1(57.59,346.27) v1(57.56,344.46) v1(58.09,353.4) v1(58.27,349.29) v1(58.3,136.02) v1(58.21,14.19) v1(58.23,11.63) v1(58.43,130.56) v1(58.4,16.47) v1(58.52,351.47) v1(58.59,347.46) v1(58.6,342.24) v1(58.58,245.53) v1(58.58,191.09) v1(58.58,160.97) v1(58.55,7.19) v1(58.62,266.34) v1(58.62,264.54) v1(58.63,247.31) v1(58.7,226.21) v1(58.6,209.19) v1(58.6,207.41) v1(58.61,189.31) v1(58.61,162.78) v1(58.61,23.67) v1(58.61,21.86) v1(58.73,228.01) v1(59.02,344.4) v1(59.28,134.18) v1(59.23,132.34) v1(59.27,18.41) v1(59.34,13.07) v1(60.07,14.82) v1(60.48,245.53) v1(60.48,226.21) v1(60.49,191.09) v1(60.49,160.97) v1(60.53,266.34) v1(60.53,264.54) v1(60.53,247.31) v1(60.51,228.01) v1(60.51,209.19) v1(60.51,207.41) v1(60.52,189.31) v1(60.52,162.78) v1(60.52,136.51) v1(60.51,134.7) v1(60.51,23.67) v1(60.51,21.86) v1(60.55,7.19) v1(60.66,11.74) v1(61.57,16.15) v1(61.66,225.55) v1(61.77,23.62) v1(61.77,13.08) v1(61.86,223.8) v1(61.99,190.94) v1(61.97,21.64) v1(62.01,221.84) v1(62.01,188.93) v1(62.15,11.51) v1(62.15,10.12) v1(62.39,245.53) v1(62.39,160.97) v1(62.43,266.34) v1(62.43,264.54) v1(62.44,247.31) v1(62.41,209.19) v1(62.41,207.41) v1(62.42,162.78) v1(62.43,136.51) v1(62.41,134.7) v1(62.48,20.74) v1(62.48,18.83) v1(62.55,7.19) v1(62.6,187.6) v1(62.6,185.7) v1(62.6,183.79) v1(62.6,181.89) v1(62.6,179.98) v1(62.6,178.08) v1(62.63,176.14) v1(62.73,227.08) v1(62.86,23.2) v1(63.07,220.25) v1(63.02,17.51) v1(63.27,190.22) v1(63.49,225.79) v1(63.46,14.2) v1(63.63,223.79) v1(63.86,209.11) v1(63.86,207.51) v1(63.82,16.11) v1(63.96,221.91) v1(63.98,174.14) v1(63.91,22.08) v1(63.93,12.35) v1(63.94,10.42) v1(64.05,189.17) v1(64.29,245.53) v1(64.3,160.97) v1(64.28,20.71) v1(64.28,18.88) v1(64.34,266.34) v1(64.34,264.54) v1(64.34,247.31) v1(64.37,187.57) v1(64.37,185.67) v1(64.37,183.76) v1(64.37,181.86) v1(64.37,179.95) v1(64.37,178.05) v1(64.33,162.78) v1(64.33,136.51) v1(64.32,134.7) v1(64.45,176.25) v1(64.65,208.32) v1(64.95,221.27) v1(64.93,219.44) v1(65.23,22.01) v1(66.2,245.53) v1(66.24,266.34) v1(66.24,264.54) v1(66.25,247.31) v1(66.22,175.34) v1(66.22,173.53) v1(66.23,162.78) v1(66.2,160.97) v1(66.24,136.51) v1(66.22,134.7) v1(66.28,22.81) v1(66.3,19.43) v1(66.3,17.52) v1(66.3,15.62) v1(66.55,7.19) v1(66.73,221.27) v1(66.71,219.44) v1(66.93,24.65) v1(67.47,32.05) v1(67.47,30.24) v1(68.01,353.42) v1(68.08,25.65) v1(68.06,18.08) v1(68.15,266.34) v1(68.15,264.54) v1(68.15,247.31) v1(68.1,245.53) v1(68.12,175.34) v1(68.12,173.53) v1(68.14,162.78) v1(68.11,160.97) v1(68.14,136.51) v1(68.13,134.7) v1(68.12,20.04) v1(68.49,351.3) v1(68.47,348.92) v1(68.49,346.7) v1(68.49,219.44) v1(68.5,221.27) v1(68.55,7.06) v1(68.79,22.93) v1(68.71,21.02) v1(68.84,23.99) v1(69.19,20.04) v1(69.13,18.08) v1(69.13,14.31) v1(69.28,345.34) v1(69.38,32.02) v1(69.41,30.27) v1(70,354.55) v1(70.04,351.28) v1(70.04,349.45) v1(70.05,347.18) v1(70.05,266.34) v1(70.05,264.54) v1(70.06,247.31) v1(70.01,245.53) v1(70.03,175.34) v1(70.03,173.53) v1(70.04,162.78) v1(70.01,160.97) v1(70.05,136.51) v1(70.03,134.7) v1(70.12,352.55) v1(70.28,221.27) v1(70.27,219.44) v1(70.22,26.27) v1(70.31,355.47) v1(70.48,29.54) v1(70.45,27.57) v1(70.55,7.19) v1(70.7,22.93) v1(70.96,19.64) v1(70.92,18.06) v1(70.96,16.19) v1(70.96,14.29) v1(70.96,10.48) v1(71.03,345.54) v1(71.02,160.42) v1(71.08,32) v1(71.29,157.14) v1(71.3,159.02) v1(71.63,25.14) v1(71.79,162.17) v1(71.88,355.53) v1(71.9,351.29) v1(71.94,349.45) v1(71.95,347.18) v1(71.96,343.74) v1(71.96,266.34) v1(71.96,264.54) v1(71.96,247.31) v1(71.91,245.53) v1(71.93,175.34) v1(71.93,173.53) v1(71.95,136.51) v1(71.94,134.7) v1(71.99,33.35) v1(71.99,19.76) v1(72.03,353.55) v1(72.06,221.27) v1(72.05,219.44) v1(72.03,155.21) v1(72.19,13.98) v1(72.16,11.14) v1(72.26,29.4) v1(72.26,27.57) v1(72.6,22.93) v1(72.78,161) v1(72.83,35.27) v1(72.86,30.24) v1(72.87,18.16) v1(72.89,16.3) v1(72.92,345.53) v1(73.08,159.01) v1(73.1,157.15) v1(73.17,356.18) v1(73.57,37.01) v1(73.79,154.04) v1(73.87,351.27) v1(73.85,349.45) v1(73.86,347.18) v1(73.86,266.34) v1(73.86,264.54) v1(73.87,247.31) v1(73.82,245.53) v1(73.84,221.27) v1(73.82,219.44) v1(73.84,175.34) v1(73.84,173.53) v1(73.87,155.96) v1(73.86,136.51) v1(73.84,134.7) v1(73.82,19.78) v1(73.84,14.01) v1(73.86,11.58) v1(73.94,354.56) v1(73.95,343.71) v1(73.91,33.2) v1(74.09,357.15) v1(74.08,341.9) v1(74.08,339.99) v1(74.08,338.09) v1(74.08,336.18) v1(74.08,334.28) v1(74.08,332.37) v1(74.18,330.43) v1(74.15,38.34) v1(74.16,31.97) v1(74.29,29.92) v1(74.49,43.95) v1(74.49,42.04) v1(74.49,40.14) v1(74.49,23.5) v1(74.55,7.19) v1(74.73,359.12) v1(74.72,35.1) v1(74.77,18.16) v1(74.8,16.3) v1(74.91,27.84) v1(74.94,25.55) v1(75.15,345.06) v1(75.38,361.03) v1(75.34,355.6) v1(75.4,31.3) v1(75.49,21.61) v1(75.54,328.38) v1(75.59,222.04) v1(75.55,219.68) v1(75.51,36.93) v1(75.78,351.27) v1(75.75,349.45) v1(75.76,347.18) v1(75.77,266.34) v1(75.77,264.54) v1(75.77,247.31) v1(75.72,245.53) v1(75.8,225.75) v1(75.71,223.79) v1(75.74,175.34) v1(75.74,173.53) v1(75.75,155.7) v1(75.74,153.92) v1(75.76,136.51) v1(75.75,134.7) v1(75.74,14.01) v1(75.77,11.58) v1(75.77,9.79) v1(75.87,343.47) v1(75.89,341.9) v1(75.89,339.99) v1(75.89,338.09) v1(75.89,336.18) v1(75.89,334.28) v1(75.89,332.37) v1(75.8,19.76) v1(75.91,357.06) v1(76.03,362.93) v1(76.01,330.59) v1(76.21,38.87) v1(76.34,43.93) v1(76.34,42.02) v1(76.34,40.12) v1(76.49,23.3) v1(76.57,358.96) v1(76.53,227.16) v1(76.51,29.75) v1(76.68,364.82) v1(76.68,18.16) v1(76.8,220.67) v1(76.71,27.84) v1(76.71,25.55) v1(76.7,16.3) v1(76.99,329.46) v1(77.02,327.18) v1(77.24,360.86) v1(77.25,20.23) v1(77.36,366.79) v1(77.45,222.02) v1(77.55,227.91) v1(77.51,223.81) v1(77.66,351.28) v1(77.66,349.45) v1(77.67,347.18) v1(77.67,266.34) v1(77.67,264.54) v1(77.68,247.31) v1(77.63,245.53) v1(77.65,175.34) v1(77.65,173.53) v1(77.66,155.7) v1(77.65,153.92) v1(77.67,136.51) v1(77.65,134.7) v1(77.65,14.01) v1(77.67,11.58) v1(77.67,9.79) v1(77.87,362.79) v1(77.87,328.74) v1(77.98,368.63) v1(77.93,226) v1(78.07,28.7) v1(78.49,21.37) v1(78.54,364.69) v1(78.58,18.16) v1(78.64,370.54) v1(78.61,16.3) v1(78.99,22.63) v1(79.06,375.24) v1(79.06,373.51) v1(79.03,371.99) v1(79.06,25.77) v1(79.19,366.6) v1(79.13,176.31) v1(79.1,24.26) v1(79.39,376.31) v1(79.32,185.73) v1(79.32,183.82) v1(79.32,181.92) v1(79.32,180.01) v1(79.32,178.11) v1(79.43,187.59) v1(79.47,27.3) v1(79.54,351.27) v1(79.56,349.45) v1(79.57,347.18) v1(79.57,328.63) v1(79.57,326.83) v1(79.58,266.34) v1(79.58,264.54) v1(79.58,247.31) v1(79.53,245.53) v1(79.56,228.26) v1(79.56,226.45) v1(79.56,155.7) v1(79.55,153.92) v1(79.57,136.51) v1(79.56,134.7) v1(79.55,14.01) v1(79.58,11.58) v1(79.58,9.79) v1(79.74,174.33) v1(79.84,368.45) v1(80.21,188.97) v1(80.4,378.24) v1(80.49,18.16) v1(80.5,370.38) v1(80.51,16.3) v1(80.72,29.76) v1(80.76,27.88) v1(80.87,375.11) v1(80.83,373.46) v1(80.82,371.86) v1(80.92,176.05) v1(81.09,185.71) v1(81.09,183.81) v1(81.09,181.9) v1(81.09,180) v1(81.09,178.09) v1(81.31,376.08) v1(81.37,352.59) v1(81.38,189.86) v1(81.49,348.86) v1(81.47,328.63) v1(81.47,326.83) v1(81.48,266.34) v1(81.48,264.54) v1(81.49,247.31) v1(81.44,245.53) v1(81.46,228.26) v1(81.46,226.45) v1(81.47,155.7) v1(81.46,153.92) v1(81.48,136.51) v1(81.46,134.7) v1(81.46,14.01) v1(81.48,11.58) v1(81.48,9.79) v1(81.6,350.29) v1(81.59,187.82) v1(81.66,346.8) v1(81.7,380.02) v1(81.79,18.13) v1(81.94,377.29) v1(82.23,27.71) v1(82.3,25.34) v1(82.41,345.65) v1(82.47,343.77) v1(82.49,16.31) v1(82.52,378.38) v1(82.99,18.17) v1(83.09,32.94) v1(83.04,31) v1(83.04,29.39) v1(83.08,22.93) v1(83.07,21.38) v1(83.03,19.58) v1(83.37,381.16) v1(83.36,354.47) v1(83.36,347.65) v1(83.38,341.67) v1(83.38,328.63) v1(83.38,326.83) v1(83.39,266.34) v1(83.39,264.54) v1(83.39,247.31) v1(83.34,245.53) v1(83.37,228.26) v1(83.37,226.45) v1(83.36,190.18) v1(83.36,188.38) v1(83.37,155.7) v1(83.36,153.92) v1(83.38,136.51) v1(83.37,134.7) v1(83.36,14.01) v1(83.39,11.58) v1(83.39,9.79) v1(83.45,378.79) v1(83.5,352.17) v1(84.24,345.72) v1(84.27,343.81) v1(84.4,17.01) v1(84.89,342.73) v1(84.87,31.05) v1(84.87,28.79) v1(84.87,26.35) v1(84.9,24.08) v1(84.84,21.79) v1(84.84,19.55) v1(84.88,18.21) v1(84.92,32.97) v1(85.27,382.39) v1(85.26,356.14) v1(85.22,340.66) v1(85.28,328.63) v1(85.28,326.83) v1(85.29,266.34) v1(85.29,264.54) v1(85.3,247.31) v1(85.25,245.53) v1(85.27,228.26) v1(85.27,226.45) v1(85.27,190.18) v1(85.27,188.38) v1(85.28,155.7) v1(85.27,153.92) v1(85.29,136.51) v1(85.27,134.7) v1(85.37,380.52) v1(85.38,353.84) v1(85.37,10.1) v1(85.51,14.5) v1(86.15,10.98) v1(87.06,357.7) v1(87.19,380.7) v1(87.18,342.39) v1(87.18,340.61) v1(87.19,328.63) v1(87.19,326.83) v1(87.2,266.34) v1(87.2,264.54) v1(87.15,245.53) v1(87.18,228.26) v1(87.18,226.45) v1(87.17,190.18) v1(87.17,188.38) v1(87.18,155.7) v1(87.17,153.92) v1(87.19,136.51) v1(87.18,134.7) v1(87.14,15.45) v1(87.11,12.14) v1(87.21,382.5) v1(87.29,355.53) v1(87.2,247.31) v1(87.44,24.06) v1(87.44,22.21) v1(88.38,359.18) v1(89.08,342.39) v1(89.09,340.61) v1(89.09,328.63) v1(89.09,326.83) v1(89.06,245.53) v1(89.08,228.26) v1(89.08,226.45) v1(89.08,190.18) v1(89.08,188.38) v1(89.09,155.7) v1(89.08,153.92) v1(89.1,136.51) v1(89.08,134.7) v1(89.09,15.55) v1(89.16,357.2) v1(89.1,266.34) v1(89.1,264.54) v1(89.11,247.31) v1(89.1,12.14) v1(89.66,361.06) v1(90.41,358.98) v1(90.99,342.39) v1(90.99,340.61) v1(91,328.63) v1(91,326.83) v1(90.96,245.53) v1(90.99,228.26) v1(90.99,226.45) v1(90.98,190.18) v1(90.98,188.38) v1(90.99,155.7) v1(90.98,153.92) v1(90.99,134.7) v1(91,15.55) v1(90.99,12.12) v1(91.01,266.34) v1(91.01,264.54) v1(91.01,247.31) v1(91,136.51) v1(91.46,362.88) v1(91.99,360.83) v1(92.83,342.42) v1(92.9,340.61) v1(92.87,245.53) v1(92.89,228.26) v1(92.89,226.45) v1(92.89,190.18) v1(92.89,188.38) v1(92.9,155.7) v1(92.89,153.92) v1(92.89,134.7) v1(92.88,12.14) v1(92.9,328.63) v1(92.9,326.83) v1(92.91,266.34) v1(92.91,264.54) v1(92.92,247.31) v1(92.91,136.51) v1(92.9,15.55) v1(93.2,343.83) v1(93.35,364.76) v1(93.89,362.75) v1(94.24,346.34) v1(94.74,366.12) v1(94.71,341.8) v1(94.77,245.53) v1(94.8,228.26) v1(94.8,226.45) v1(94.79,190.18) v1(94.79,188.38) v1(94.79,153.92) v1(94.8,134.7) v1(94.83,363.67) v1(94.82,266.34) v1(94.82,264.54) v1(94.82,247.31) v1(94.8,155.7) v1(94.81,136.51) v1(94.81,15.55) v1(94.82,12.12) v1(95,343.78) v1(95.49,345.06) v1(95.66,366.87) v1(95.85,364.71) v1(96.68,367.23) v1(96.69,347.31) v1(96.69,345.52) v1(96.68,245.53) v1(96.7,190.18) v1(96.7,188.38) v1(96.7,153.92) v1(96.78,365.38) v1(96.72,266.34) v1(96.72,264.54) v1(96.73,247.31) v1(96.7,228.26) v1(96.7,226.45) v1(96.71,155.7) v1(96.72,136.51) v1(96.7,134.7) v1(96.71,15.55) v1(96.76,12.47) v1(98.59,347.31) v1(98.59,345.52) v1(98.58,245.53) v1(98.61,367.28) v1(98.61,365.45) v1(98.63,266.34) v1(98.63,264.54) v1(98.63,247.31) v1(98.61,228.26) v1(98.61,226.45) v1(98.6,190.18) v1(98.6,188.38) v1(98.61,155.7) v1(98.6,153.92) v1(98.78,16.21) v1(98.73,13.55) v1(99.36,19.97) v1(99.33,18.06) v1(100.49,245.53) v1(100.48,13.76) v1(100.52,367.28) v1(100.51,365.45) v1(100.53,266.34) v1(100.53,264.54) v1(100.54,247.31) v1(100.51,228.26) v1(100.51,226.45) v1(100.51,190.18) v1(100.51,188.38) v1(100.52,155.7) v1(100.51,153.92) v1(100.89,16.07) v1(101.11,19.95) v1(101.13,18.01) v1(102.39,245.53) v1(102.42,367.28) v1(102.42,365.45) v1(102.44,247.31) v1(102.42,228.26) v1(102.42,226.45) v1(102.41,190.18) v1(102.41,188.38) v1(102.43,155.71) v1(102.42,153.91) v1(102.4,15.59) v1(102.45,13.79) v1(104.3,245.53) v1(104.35,247.31) v1(104.32,228.26) v1(104.32,226.45) v1(104.34,15.54) v1(104.34,13.74) v1(106.24,15.55) v1(106.25,13.76) v1(106.76,227.47) v1(107.38,246.44) v2(12.99,348.21) v2(12.99,346.21) v2(14.72,349.2) v2(14.72,345.22) v2(14.97,266.47) v2(14.97,264.47) v2(15.4,190.27) v2(15.4,188.27) v2(15.4,155.67) v2(15.4,153.68) v2(15.4,136.62) v2(15.4,134.63) v2(15.93,228.37) v2(15.93,226.37) v2(16.45,348.21) v2(16.45,346.21) v2(16.69,267.46) v2(16.69,263.47) v2(16.66,247.42) v2(16.66,245.42) v2(17.12,191.26) v2(17.12,187.27) v2(17.12,156.67) v2(17.12,152.68) v2(17.12,137.62) v2(17.12,133.63) v2(17.66,229.36) v2(17.66,225.37) v2(18.3,209.32) v2(18.3,207.32) v2(18.39,248.41) v2(18.39,244.42) v2(18.42,266.47) v2(18.42,264.47) v2(18.85,190.27) v2(18.85,188.27) v2(18.85,155.67) v2(18.85,153.68) v2(18.85,136.62) v2(18.85,134.63) v2(19.38,228.37) v2(19.38,226.37) v2(20.03,210.31) v2(20.03,206.32) v2(20.16,329.68) v2(20.16,327.69) v2(20.11,247.42) v2(20.11,245.42) v2(21.75,209.32) v2(21.75,207.32) v2(21.89,330.68) v2(21.89,326.69) v2(22.54,15.64) v2(22.54,13.65) v2(23.61,329.68) v2(23.61,327.69) v2(24.27,16.64) v2(24.27,12.65) v2(26,15.64) v2(26,13.65) v2(28.4,380.52) v2(28.4,378.53) v2(28.4,360.35) v2(28.4,358.35) v2(30.12,381.52) v2(30.12,377.53) v2(30.13,361.34) v2(30.13,357.36) v2(31.85,380.52) v2(31.85,378.53) v2(31.85,360.35) v2(31.85,358.35) v2(33.88,31.28) v2(34.88,33.01) v2(34.88,29.56) v2(36.15,316.34) v2(36.87,33.01) v2(36.87,29.56) v2(37.15,318.06) v2(37.15,314.61) v2(37.87,31.28) v2(39.14,318.06) v2(39.14,314.61) v2(40.14,316.34) v2(42.2,41.69) v2(43.2,43.41) v2(43.2,39.96) v2(45.19,43.41) v2(45.19,39.96) v2(46.19,41.69) v2(46.27,388.67) v2(47.26,390.4) v2(47.26,386.94) v2(49.26,390.4) v2(49.26,386.94) v2(50.25,388.67) v2(53.66,43.95) v2(54.65,45.68) v2(54.65,42.23) v2(56.65,45.68) v2(56.65,42.23) v2(57.64,43.95) v2(62.04,32.13) v2(62.04,30.13) v2(63.77,33.12) v2(63.77,29.14) v2(65.49,32.13) v2(65.49,30.13) v2(73.43,47.46) v2(74.43,49.19) v2(74.43,45.74) v2(76.42,49.19) v2(76.42,45.74) v2(77.42,47.46) v2(82.03,36.34) v2(83.02,38.06) v2(83.02,34.61) v2(85.02,38.06) v2(85.02,34.61) v2(86.02,36.34) v2(88.77,24.14) v2(88.75,22.14) v2(89.43,382.58) v2(89.43,380.58) v2(90.48,21.14) v2(90.5,25.12) v2(91.16,383.58) v2(91.16,379.59) v2(92.22,24.12) v2(92.21,22.12) v2(92.89,382.58) v2(92.89,380.58) v2(95.05,328.72) v2(95.05,326.72) v2(96.78,329.72) v2(96.78,325.73) v2(98.25,22.84) v2(98.5,328.72) v2(98.5,326.72) v2(99.25,24.56) v2(99.25,21.11) v2(99.42,136.62) v2(99.42,134.63) v2(101.02,347.41) v2(101.02,345.42) v2(101.15,137.62) v2(101.15,133.63) v2(101.24,24.56) v2(101.24,21.11) v2(102.24,22.84) v2(102.75,348.41) v2(102.75,344.42) v2(102.79,266.44) v2(102.79,264.45) v2(102.87,136.62) v2(102.87,134.63) v2(104.09,367.36) v2(104.09,365.37) v2(104.47,347.41) v2(104.47,345.42) v2(104.51,267.44) v2(104.51,263.45) v2(105.2,190.27) v2(105.2,188.27) v2(105.21,155.67) v2(105.21,153.68) v2(105.82,368.36) v2(105.82,364.37) v2(106.24,266.44) v2(106.24,264.45) v2(106.92,191.26) v2(106.92,187.27) v2(106.94,156.67) v2(106.94,152.68) v2(107.55,367.36) v2(107.55,365.37) v2(108.56,15.64) v2(108.56,13.65) v2(108.65,190.27) v2(108.65,188.27) v2(108.66,155.67) v2(108.66,153.68) v2(110.28,16.64) v2(110.28,12.65) v2(112.01,15.64) v2(112.01,13.65)
